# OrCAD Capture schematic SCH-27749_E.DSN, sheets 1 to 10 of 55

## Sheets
1 Cover Page: title: T4240RDB-PB; rev: E; note: SCH-27749     /     PDF: SPF-27749
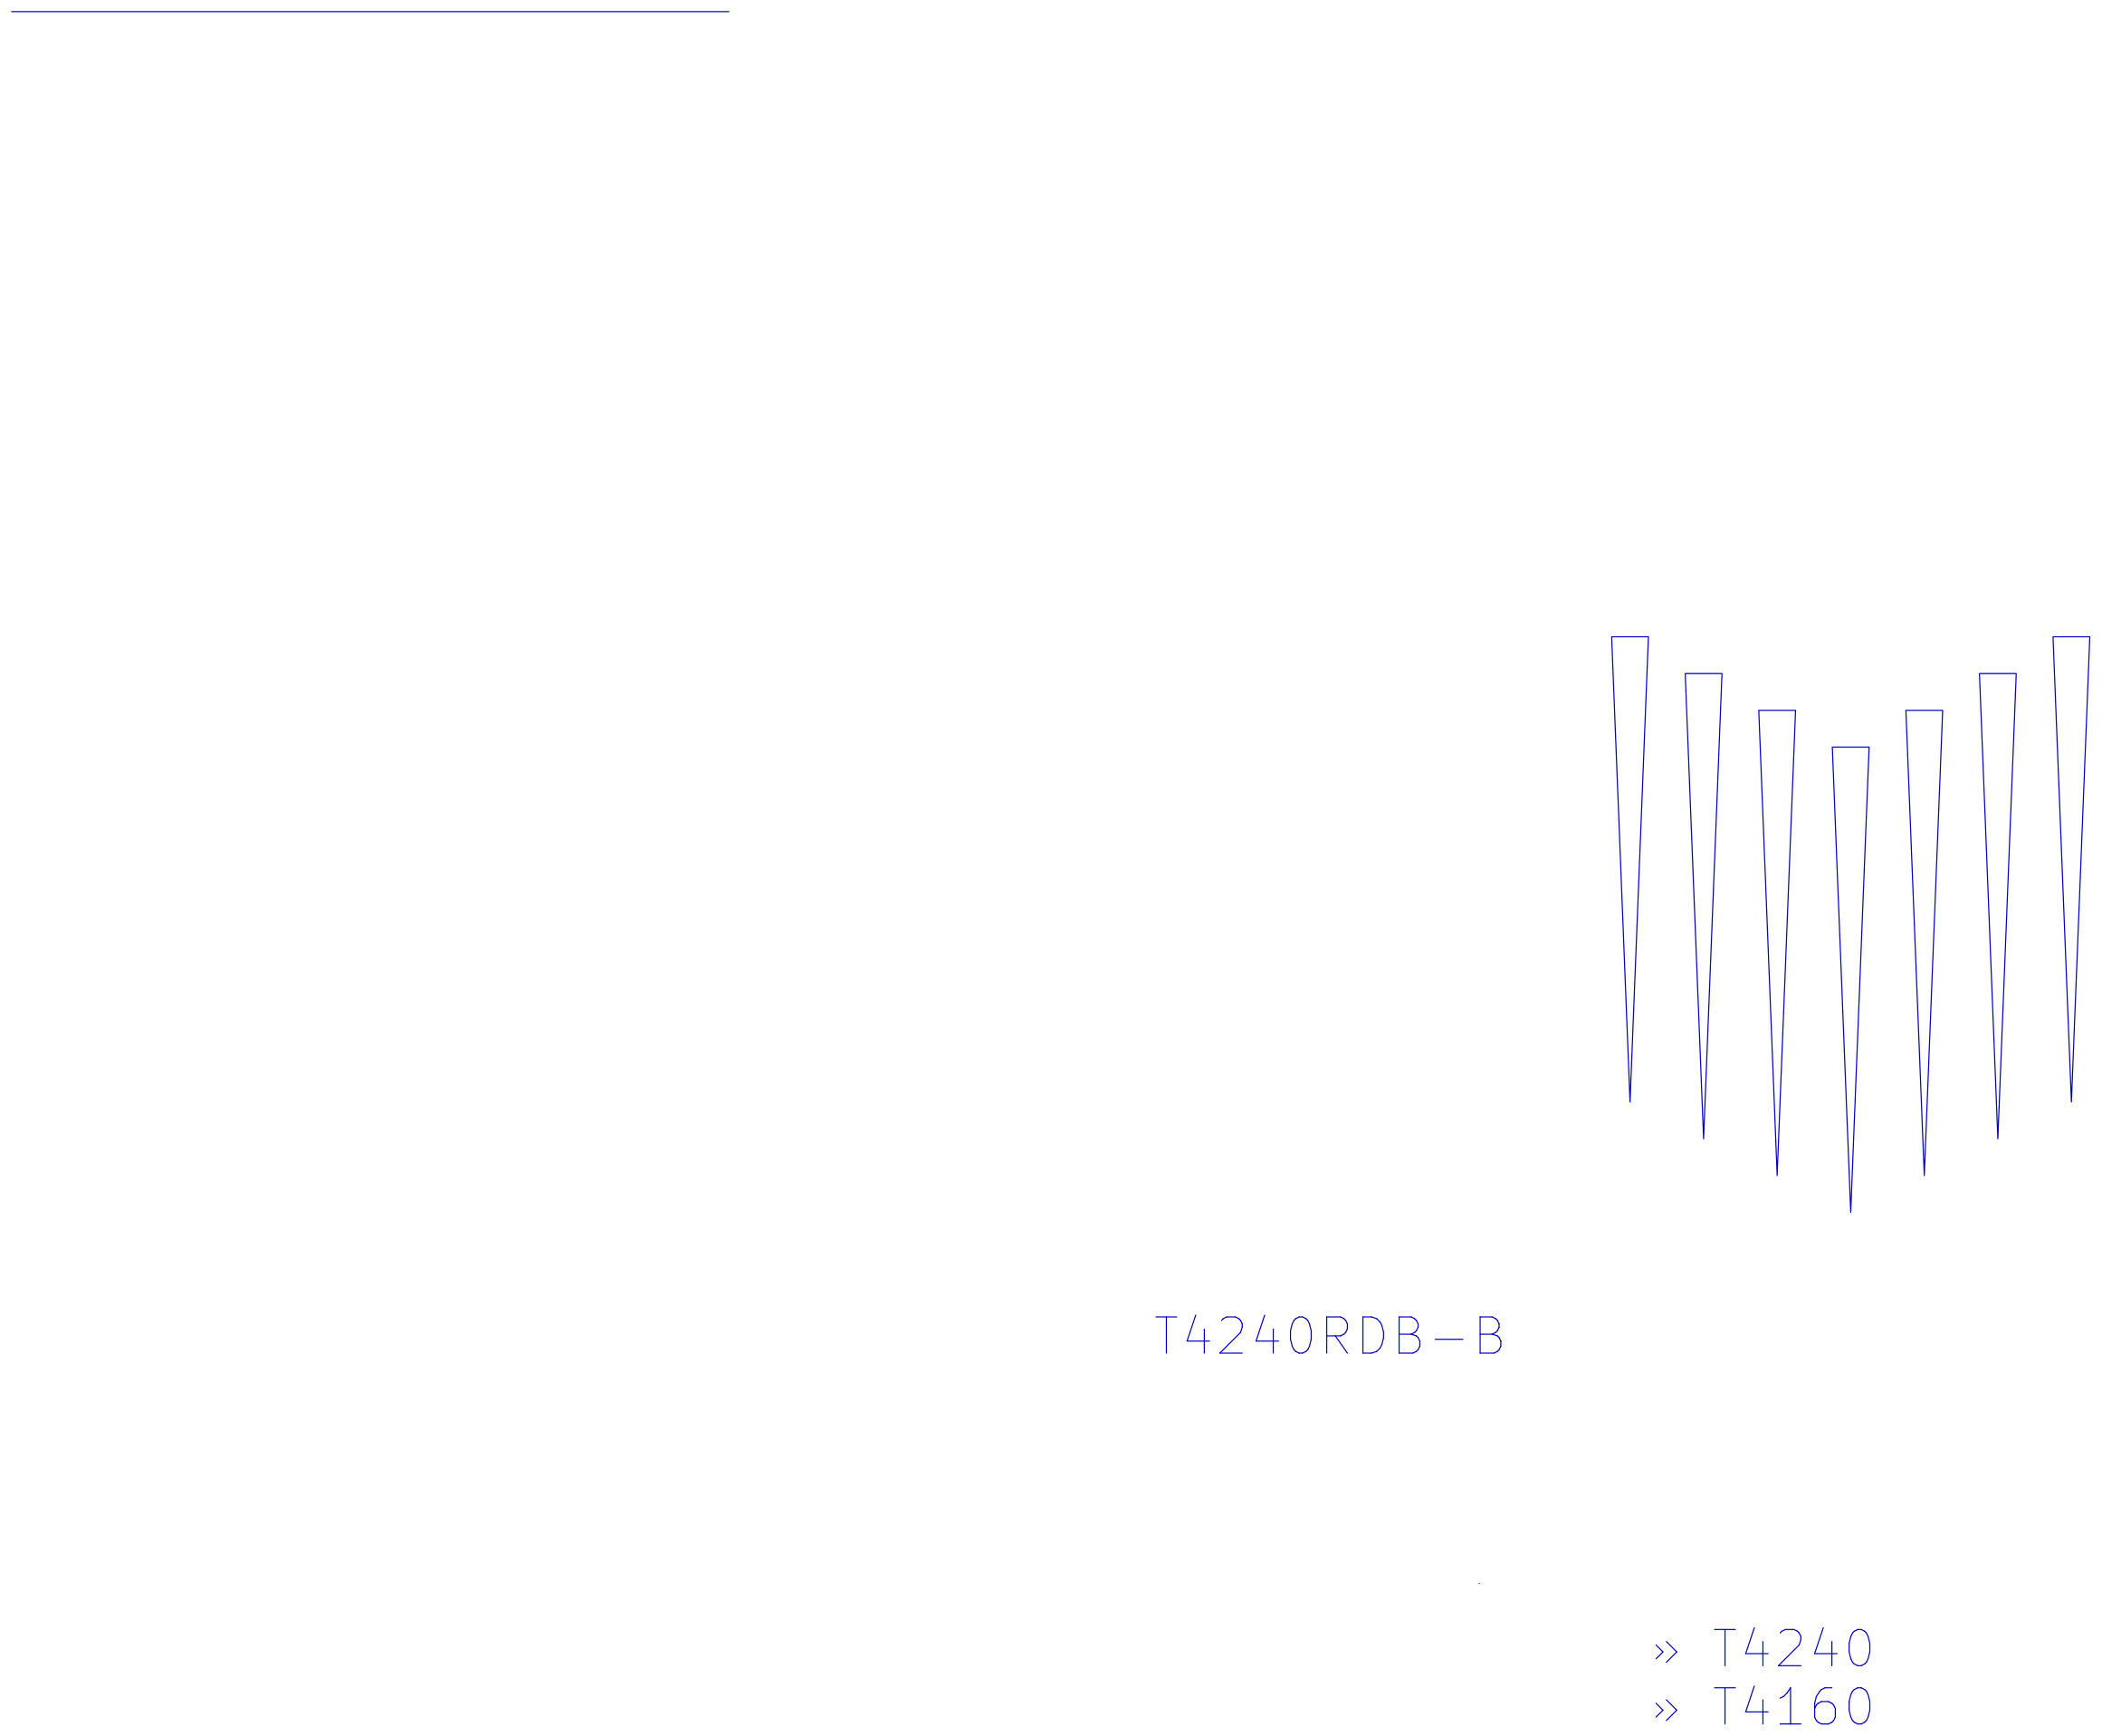
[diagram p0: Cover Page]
2 Revision Control
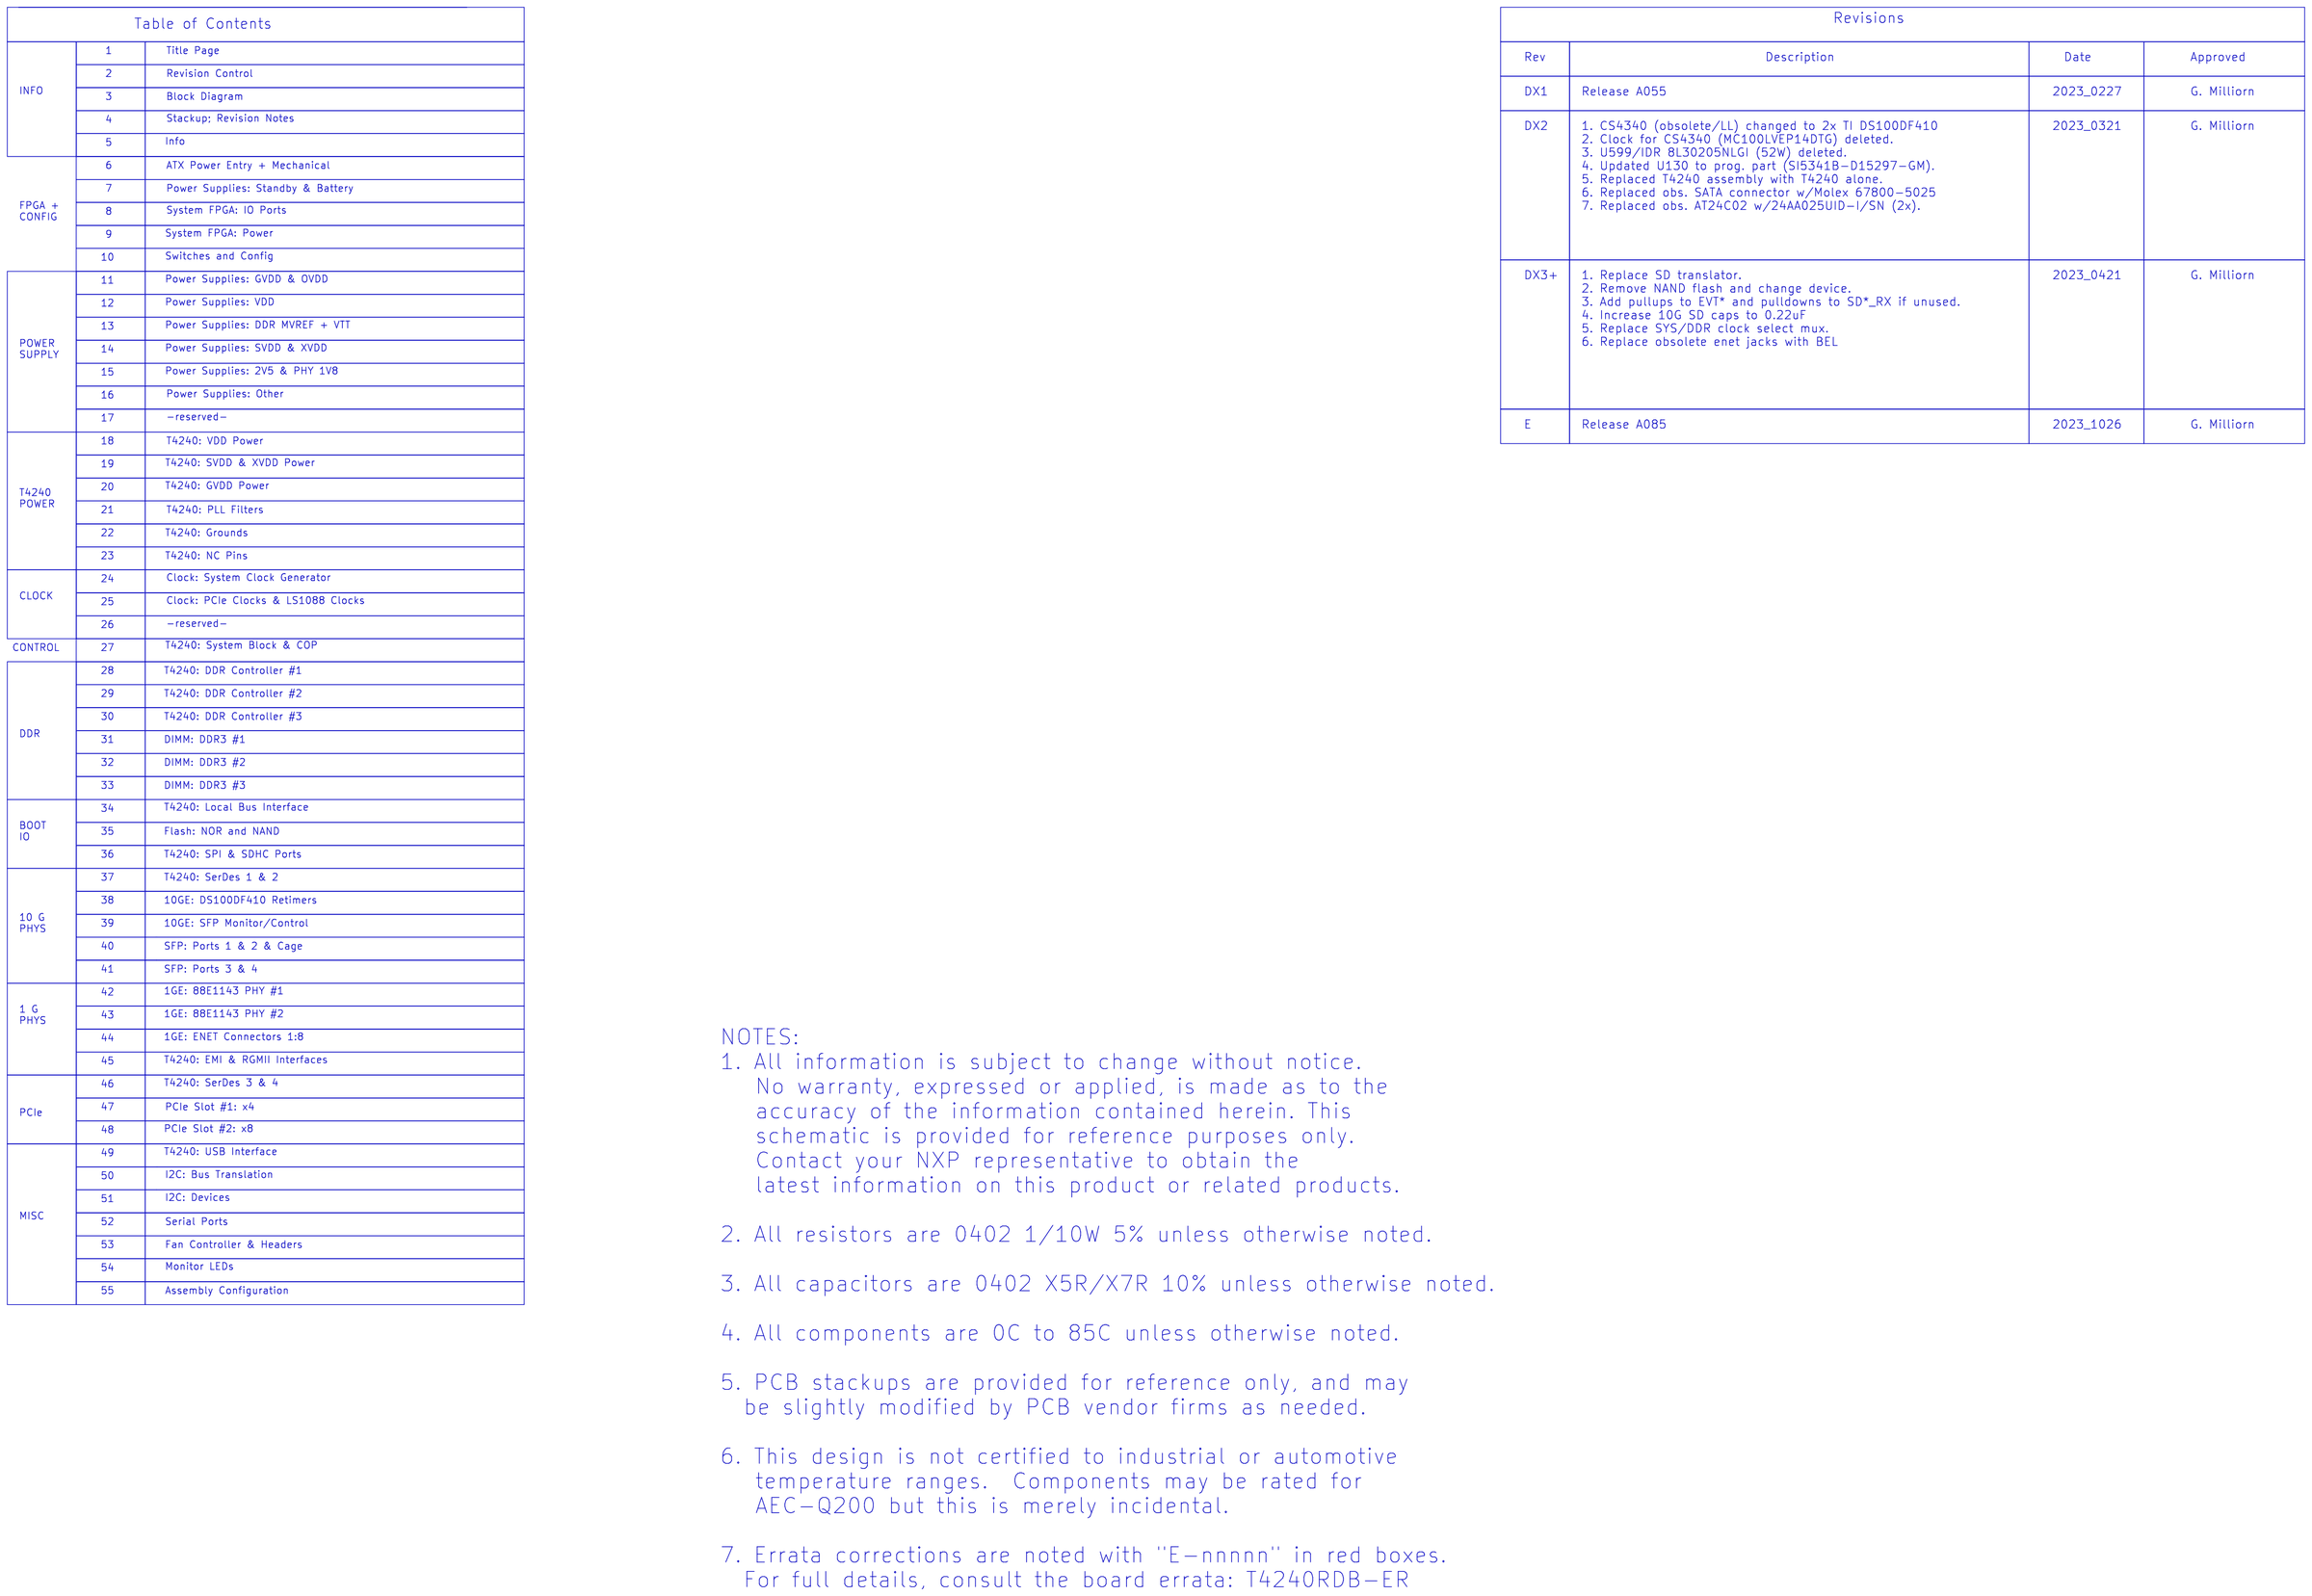
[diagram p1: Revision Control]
3 Block Diagram
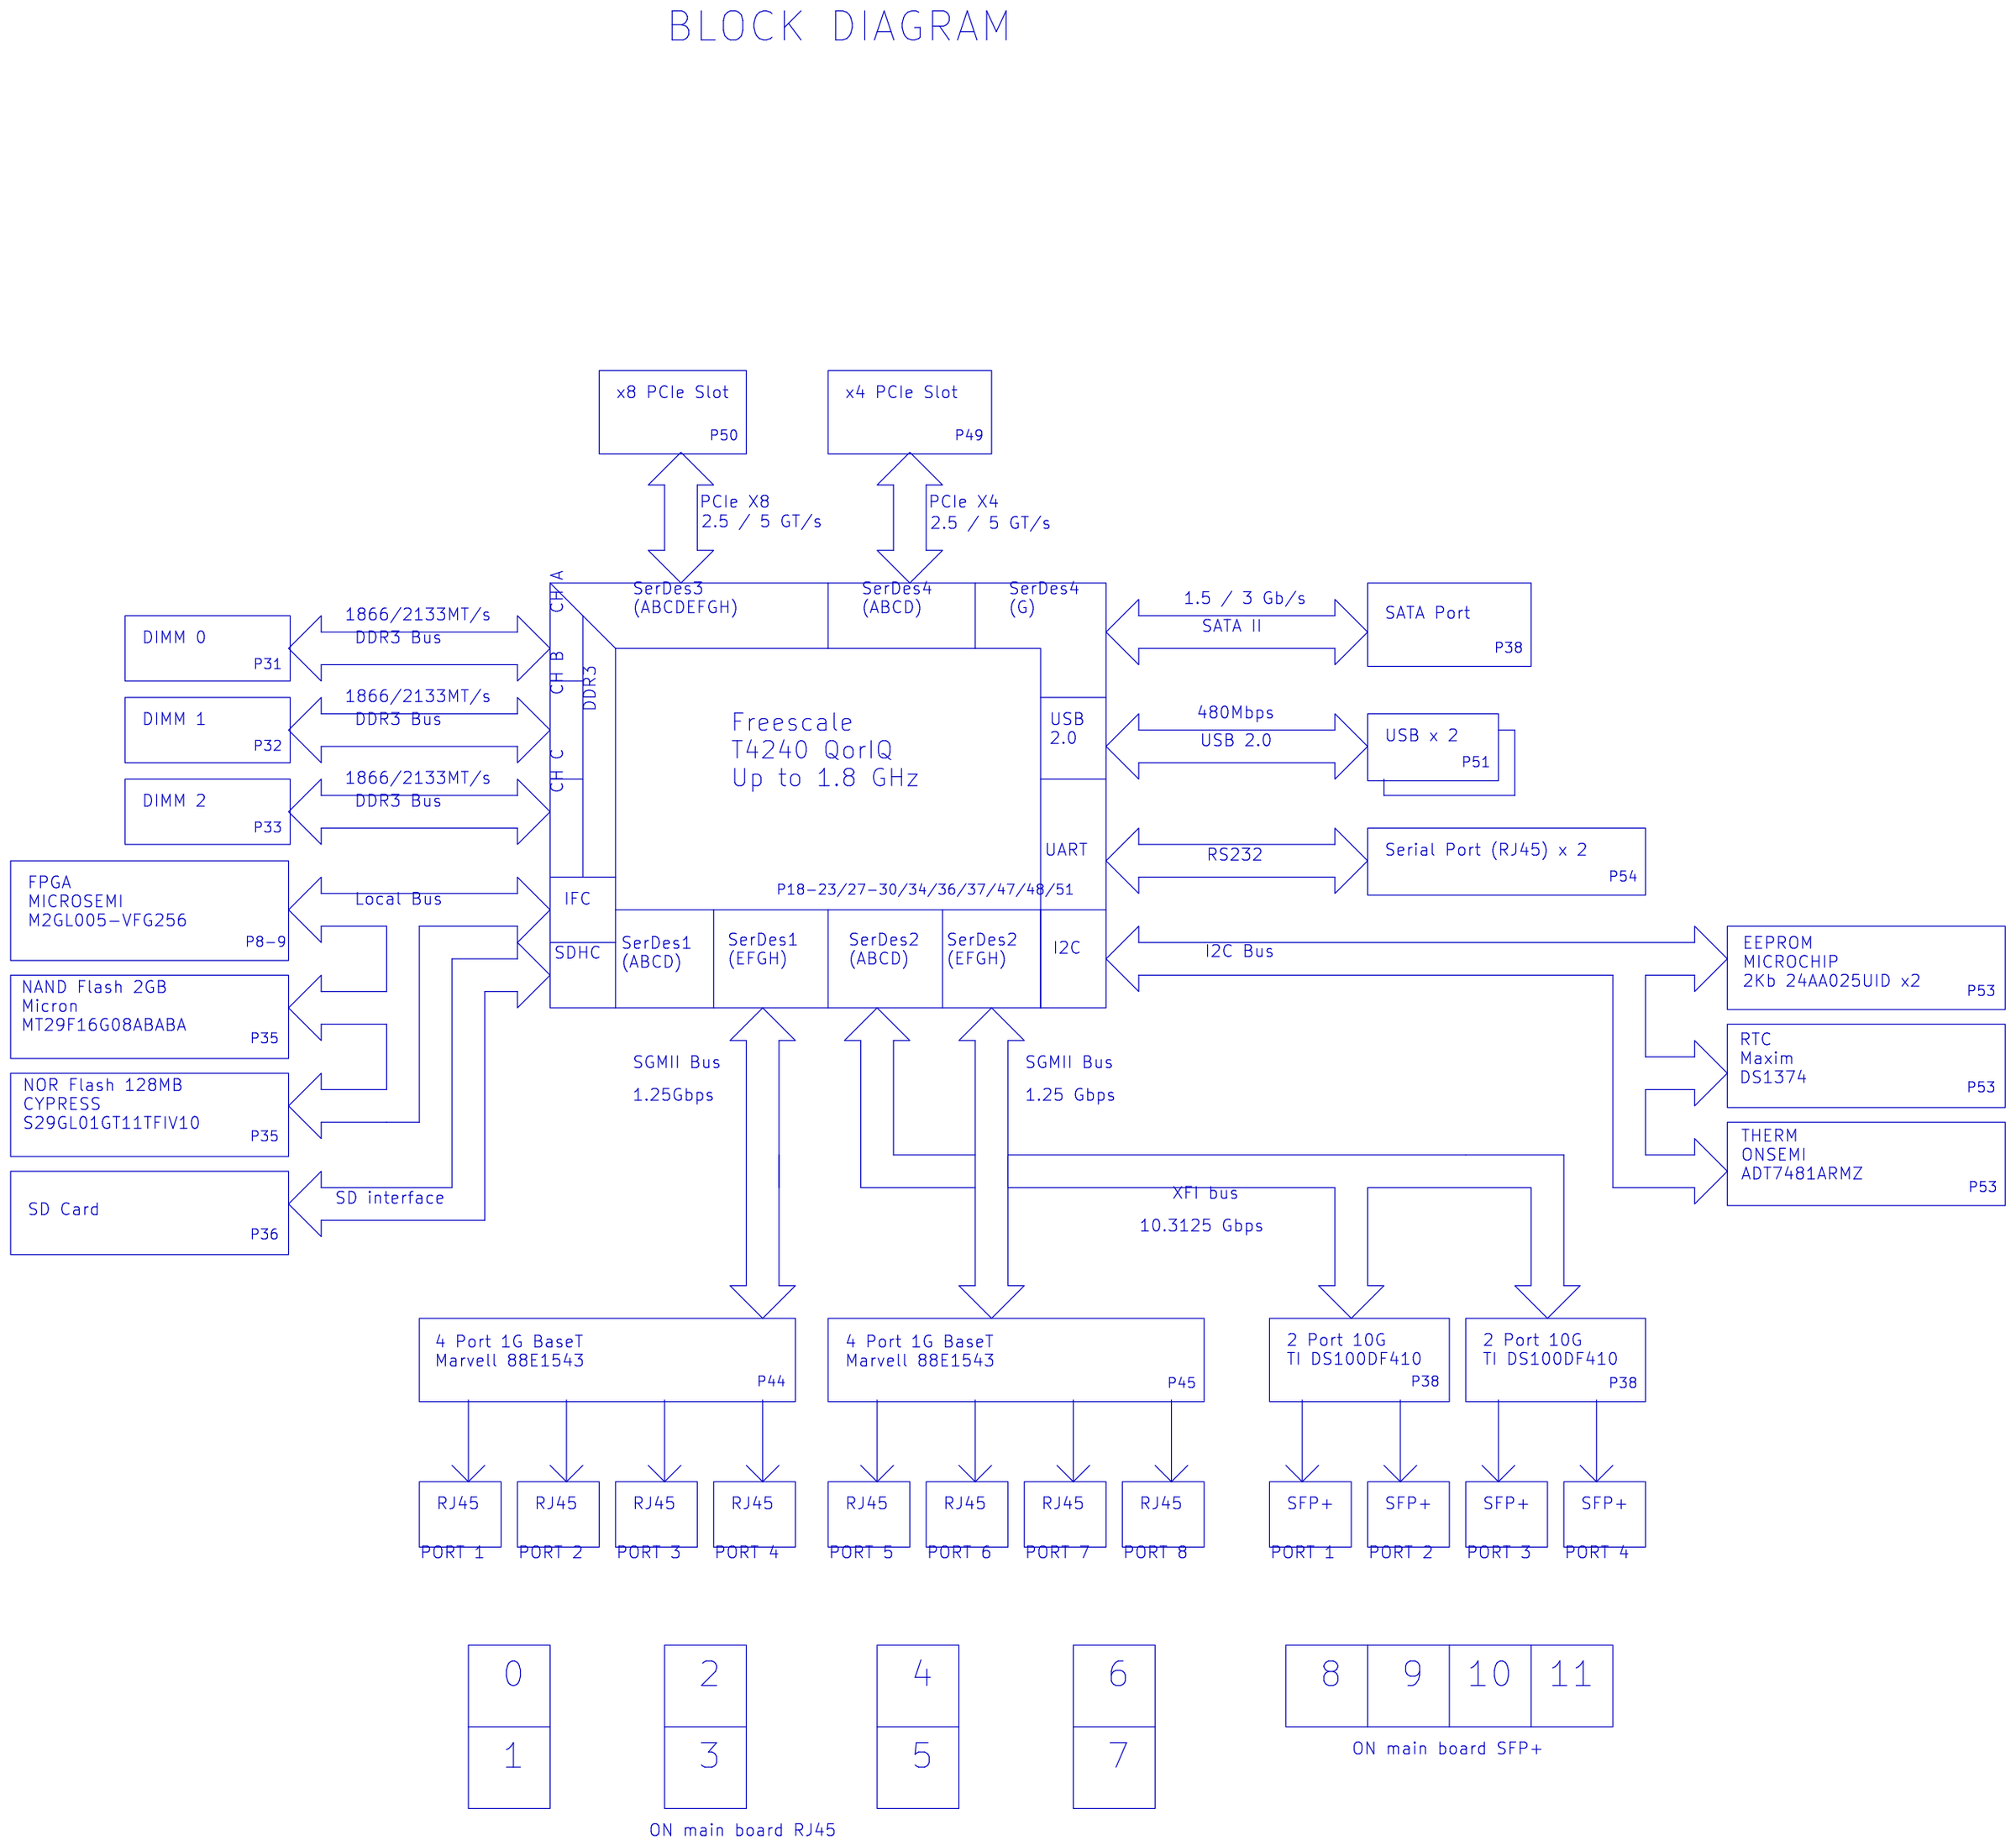
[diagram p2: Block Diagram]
4 Stackup
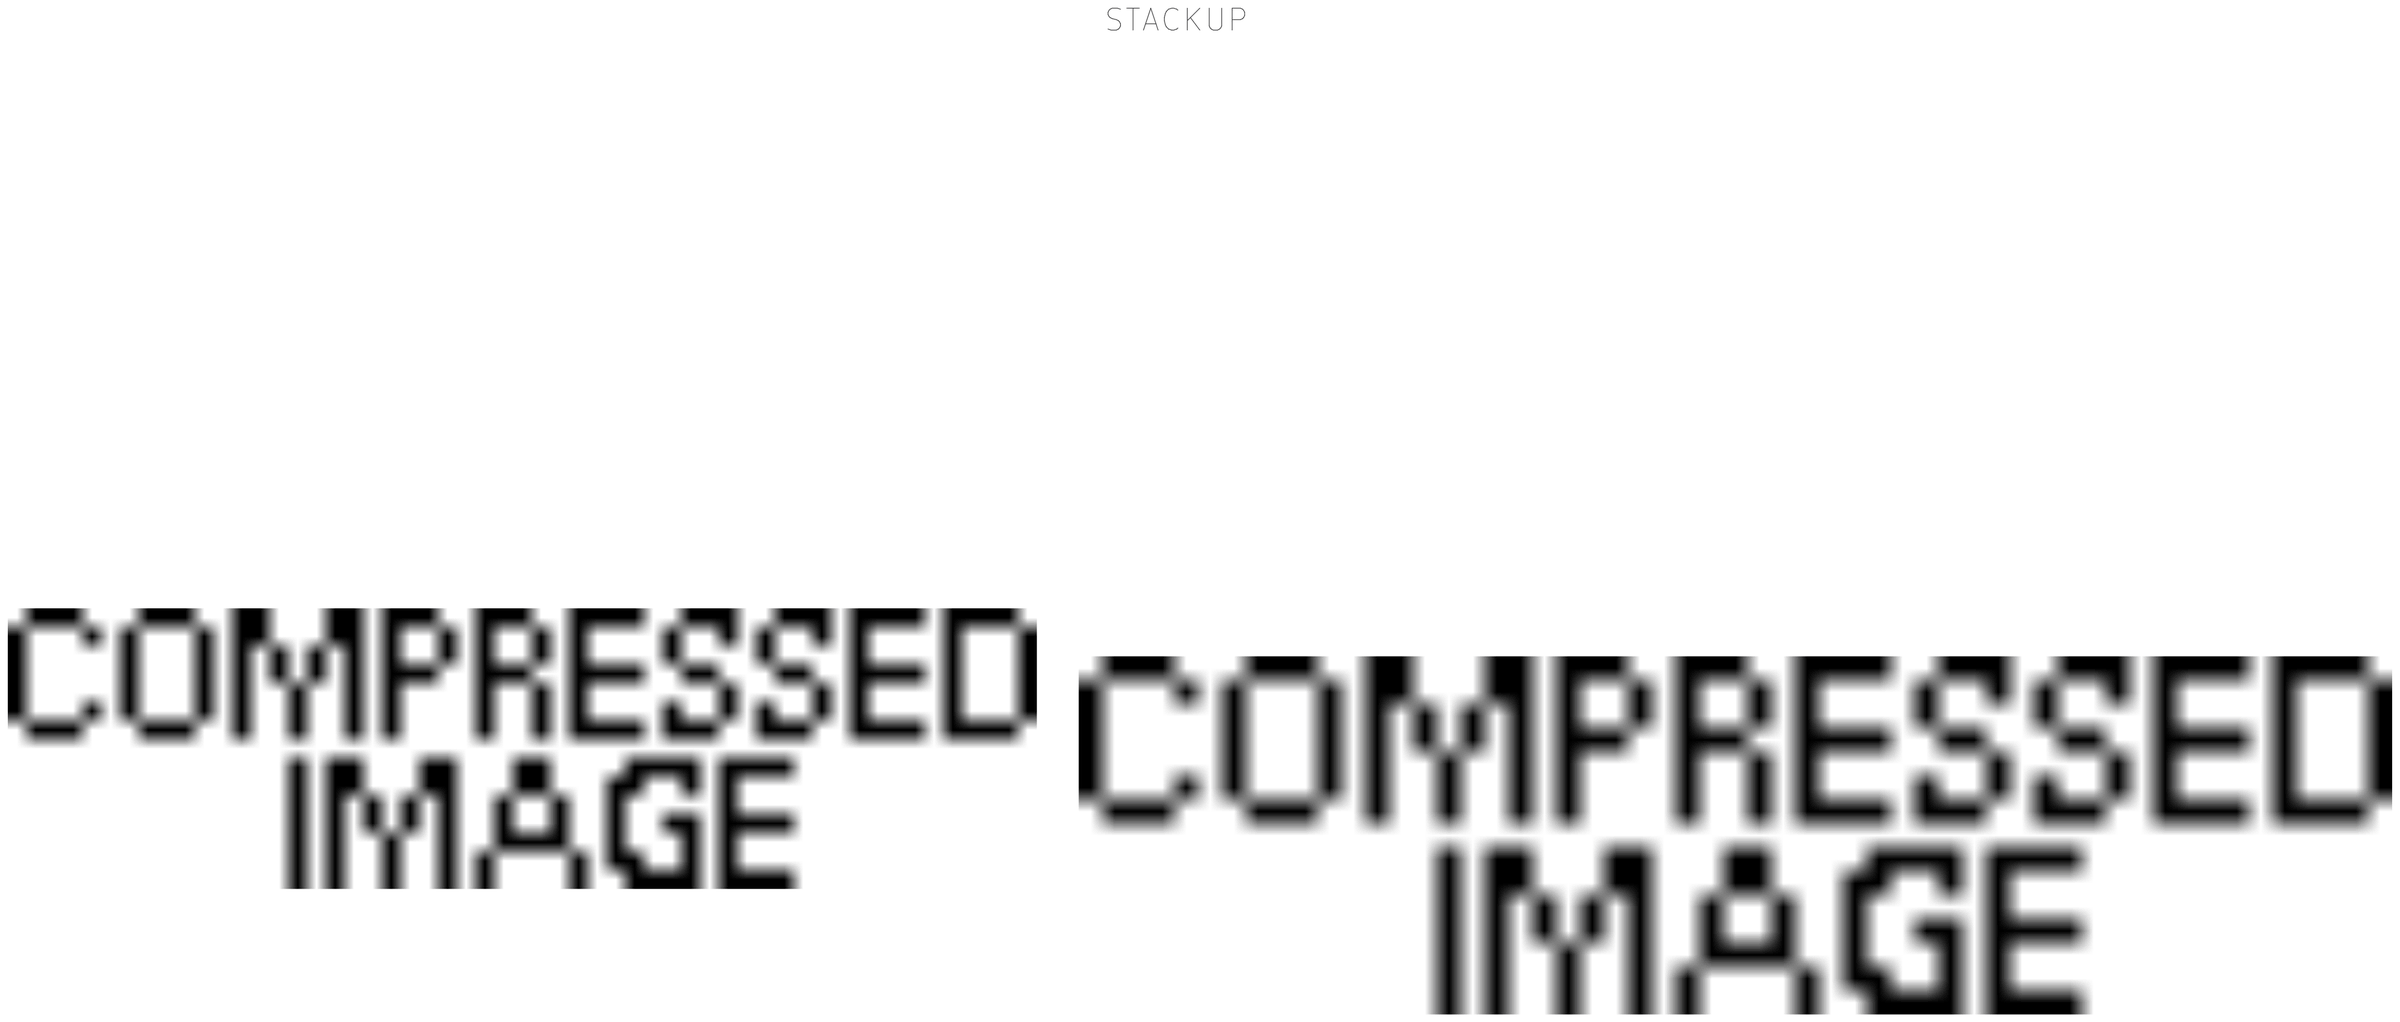
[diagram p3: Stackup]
5 Info
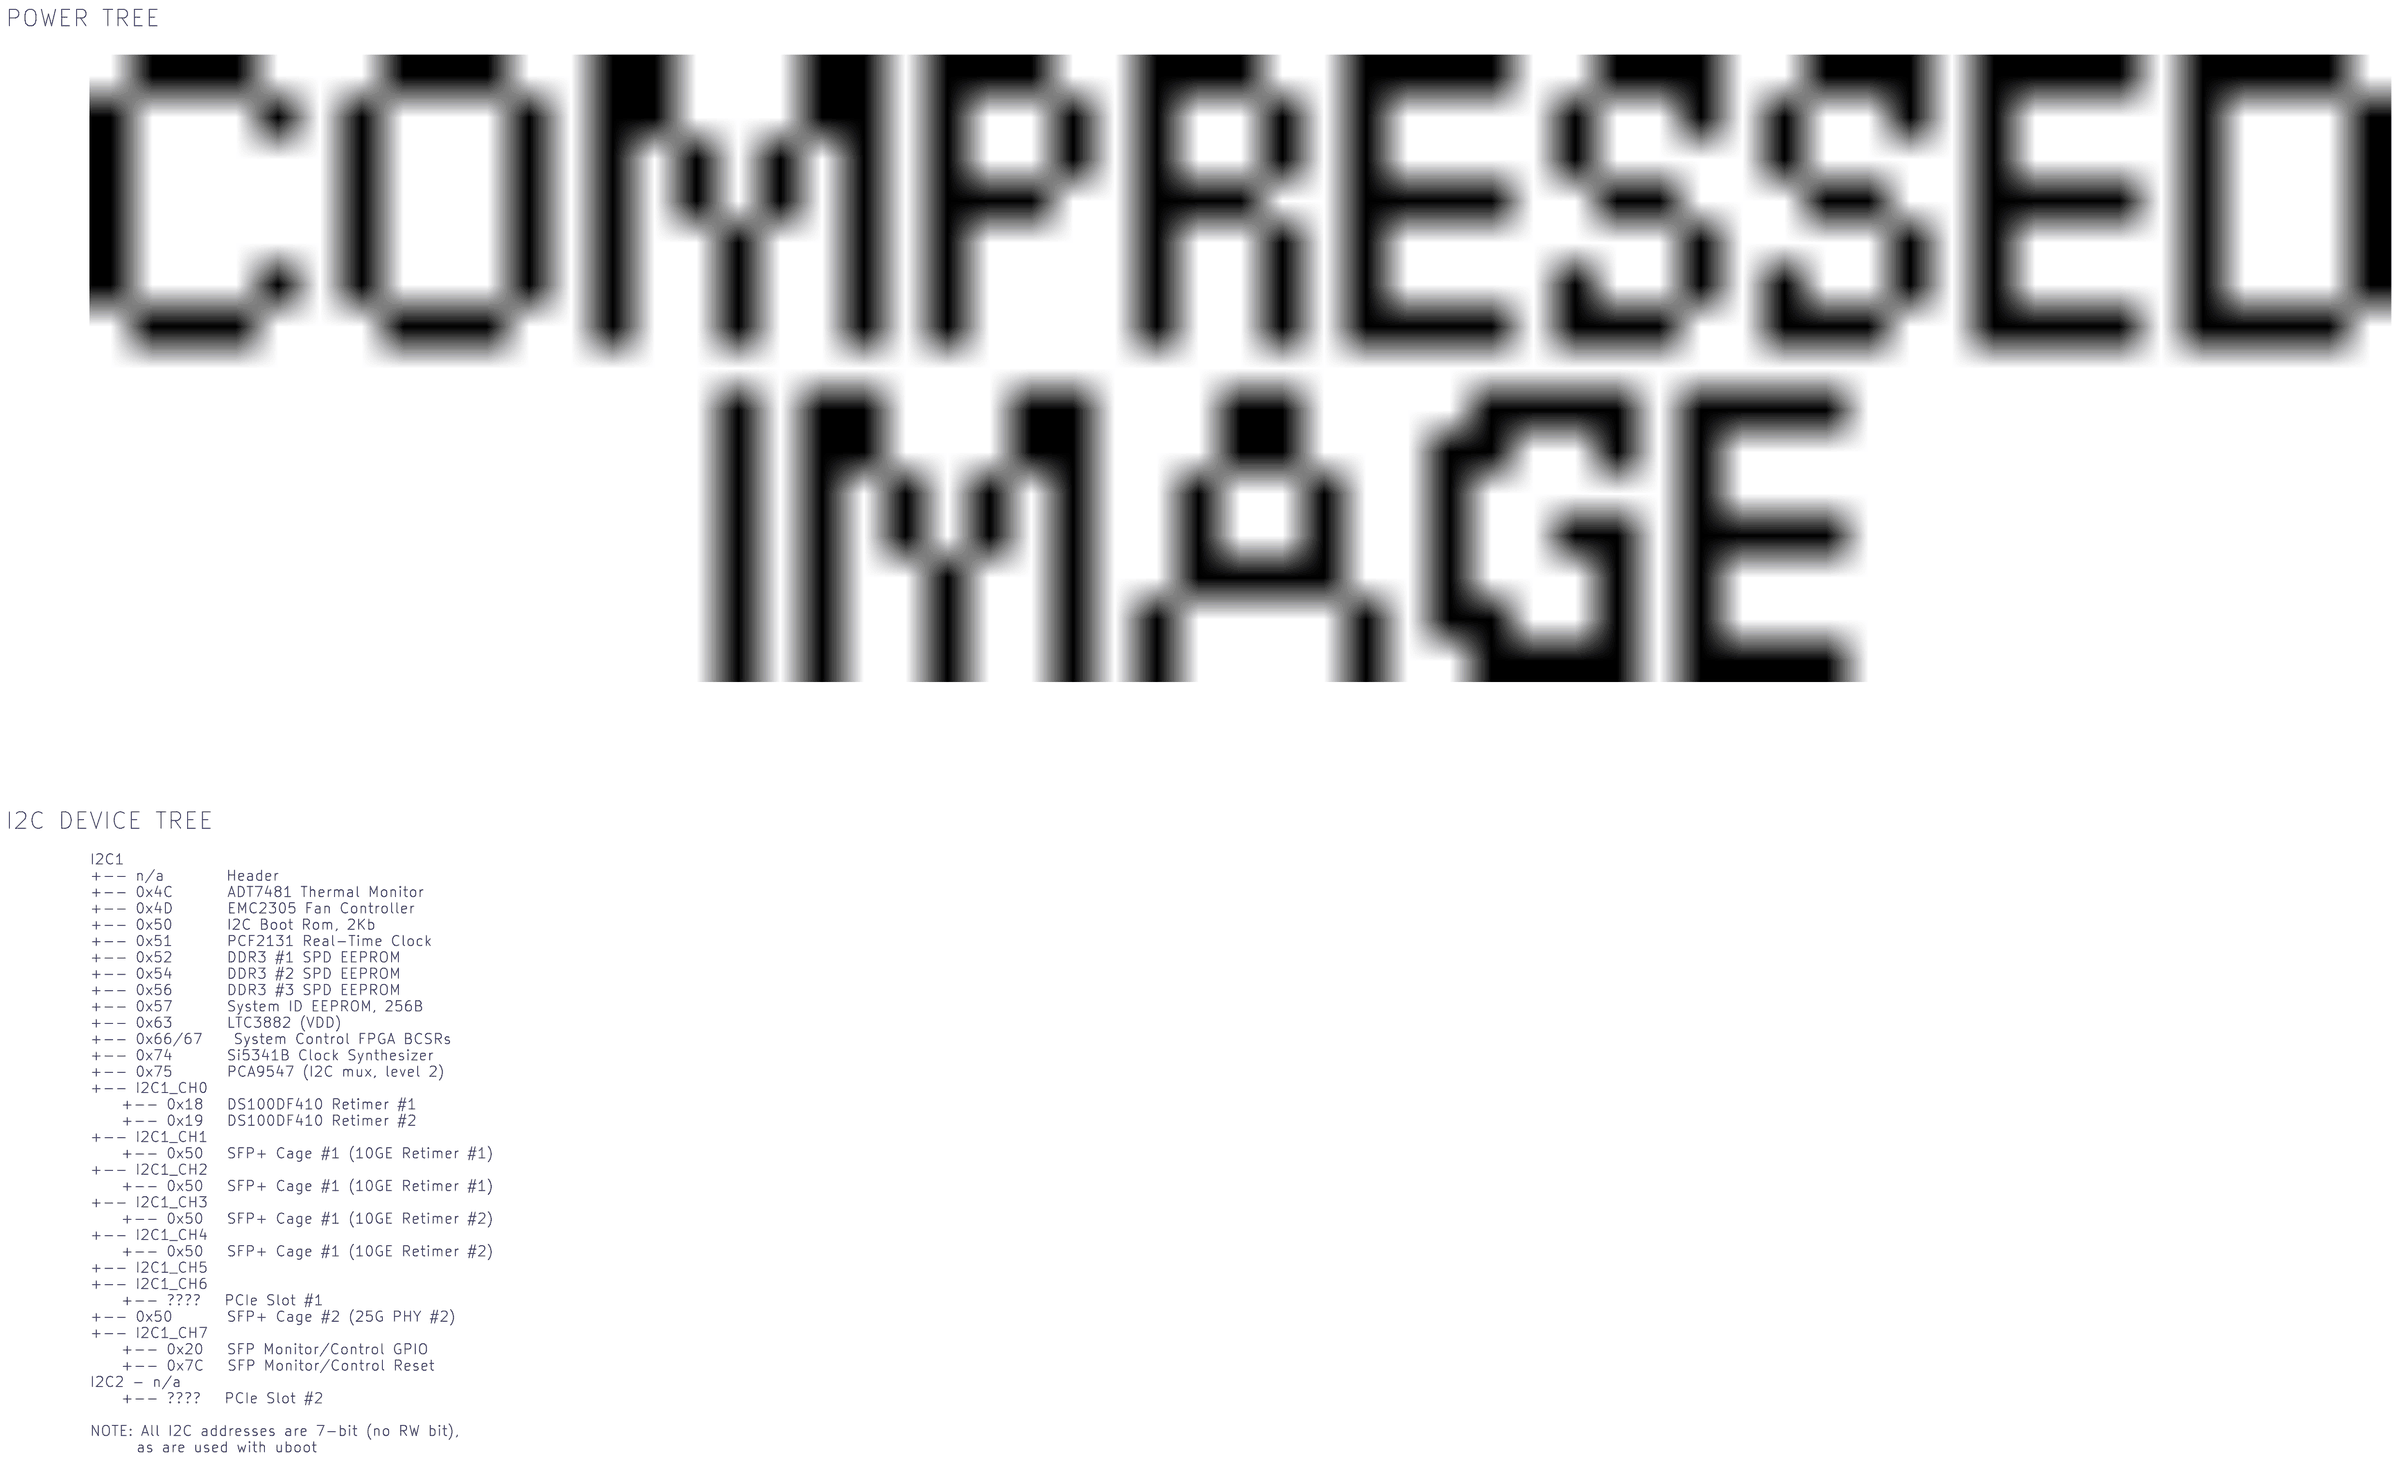
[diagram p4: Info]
6 Power Entry & Mechanical: size C
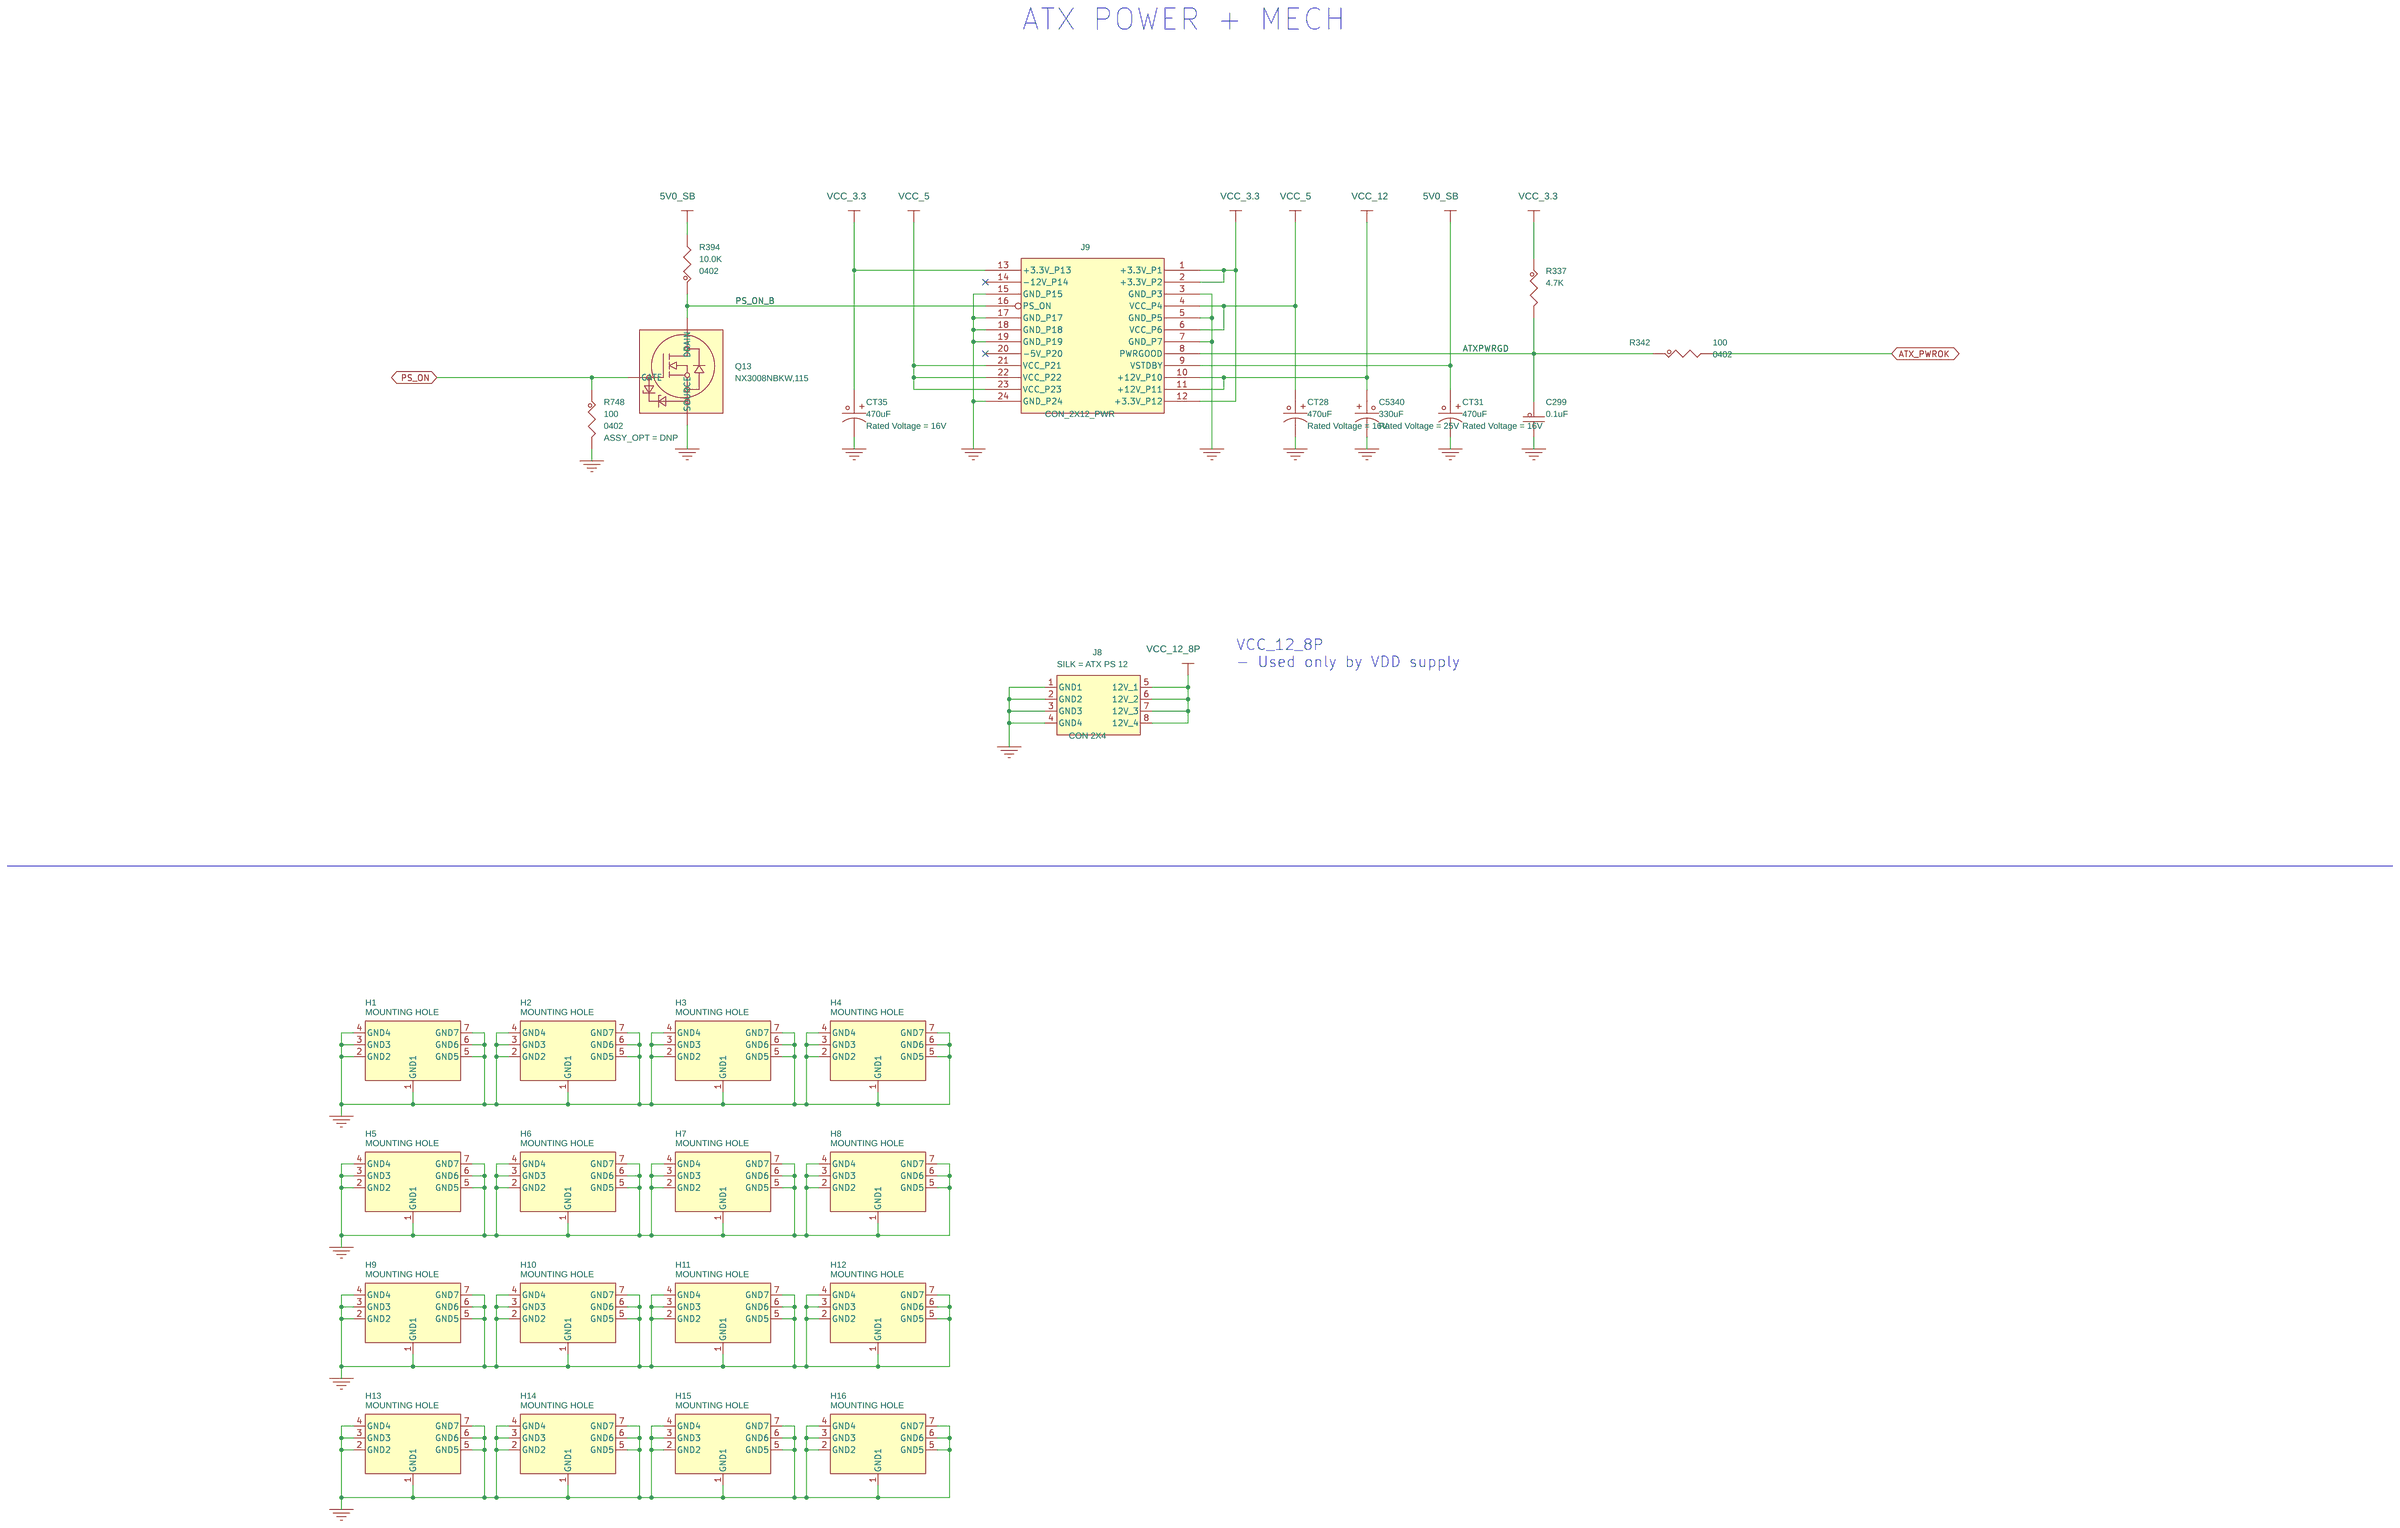
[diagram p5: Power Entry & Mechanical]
7 Standby Power: size C
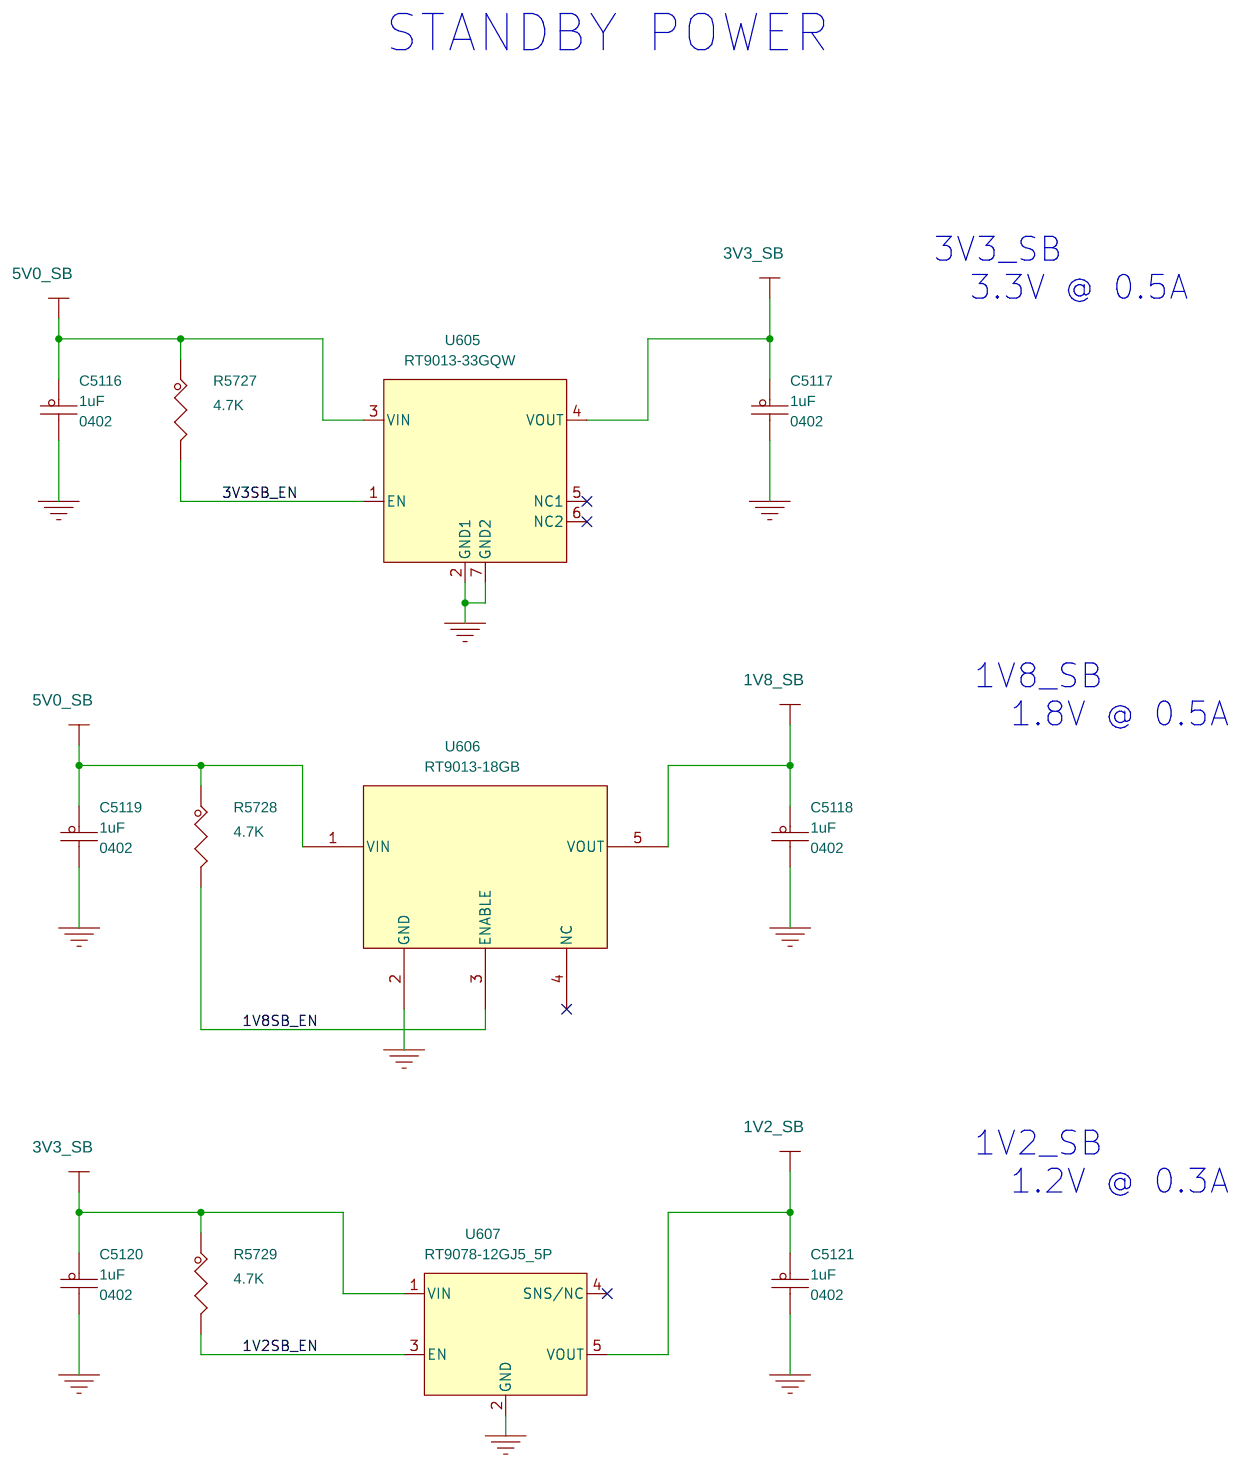
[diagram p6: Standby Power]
8 System FPGA IO Ports: size C
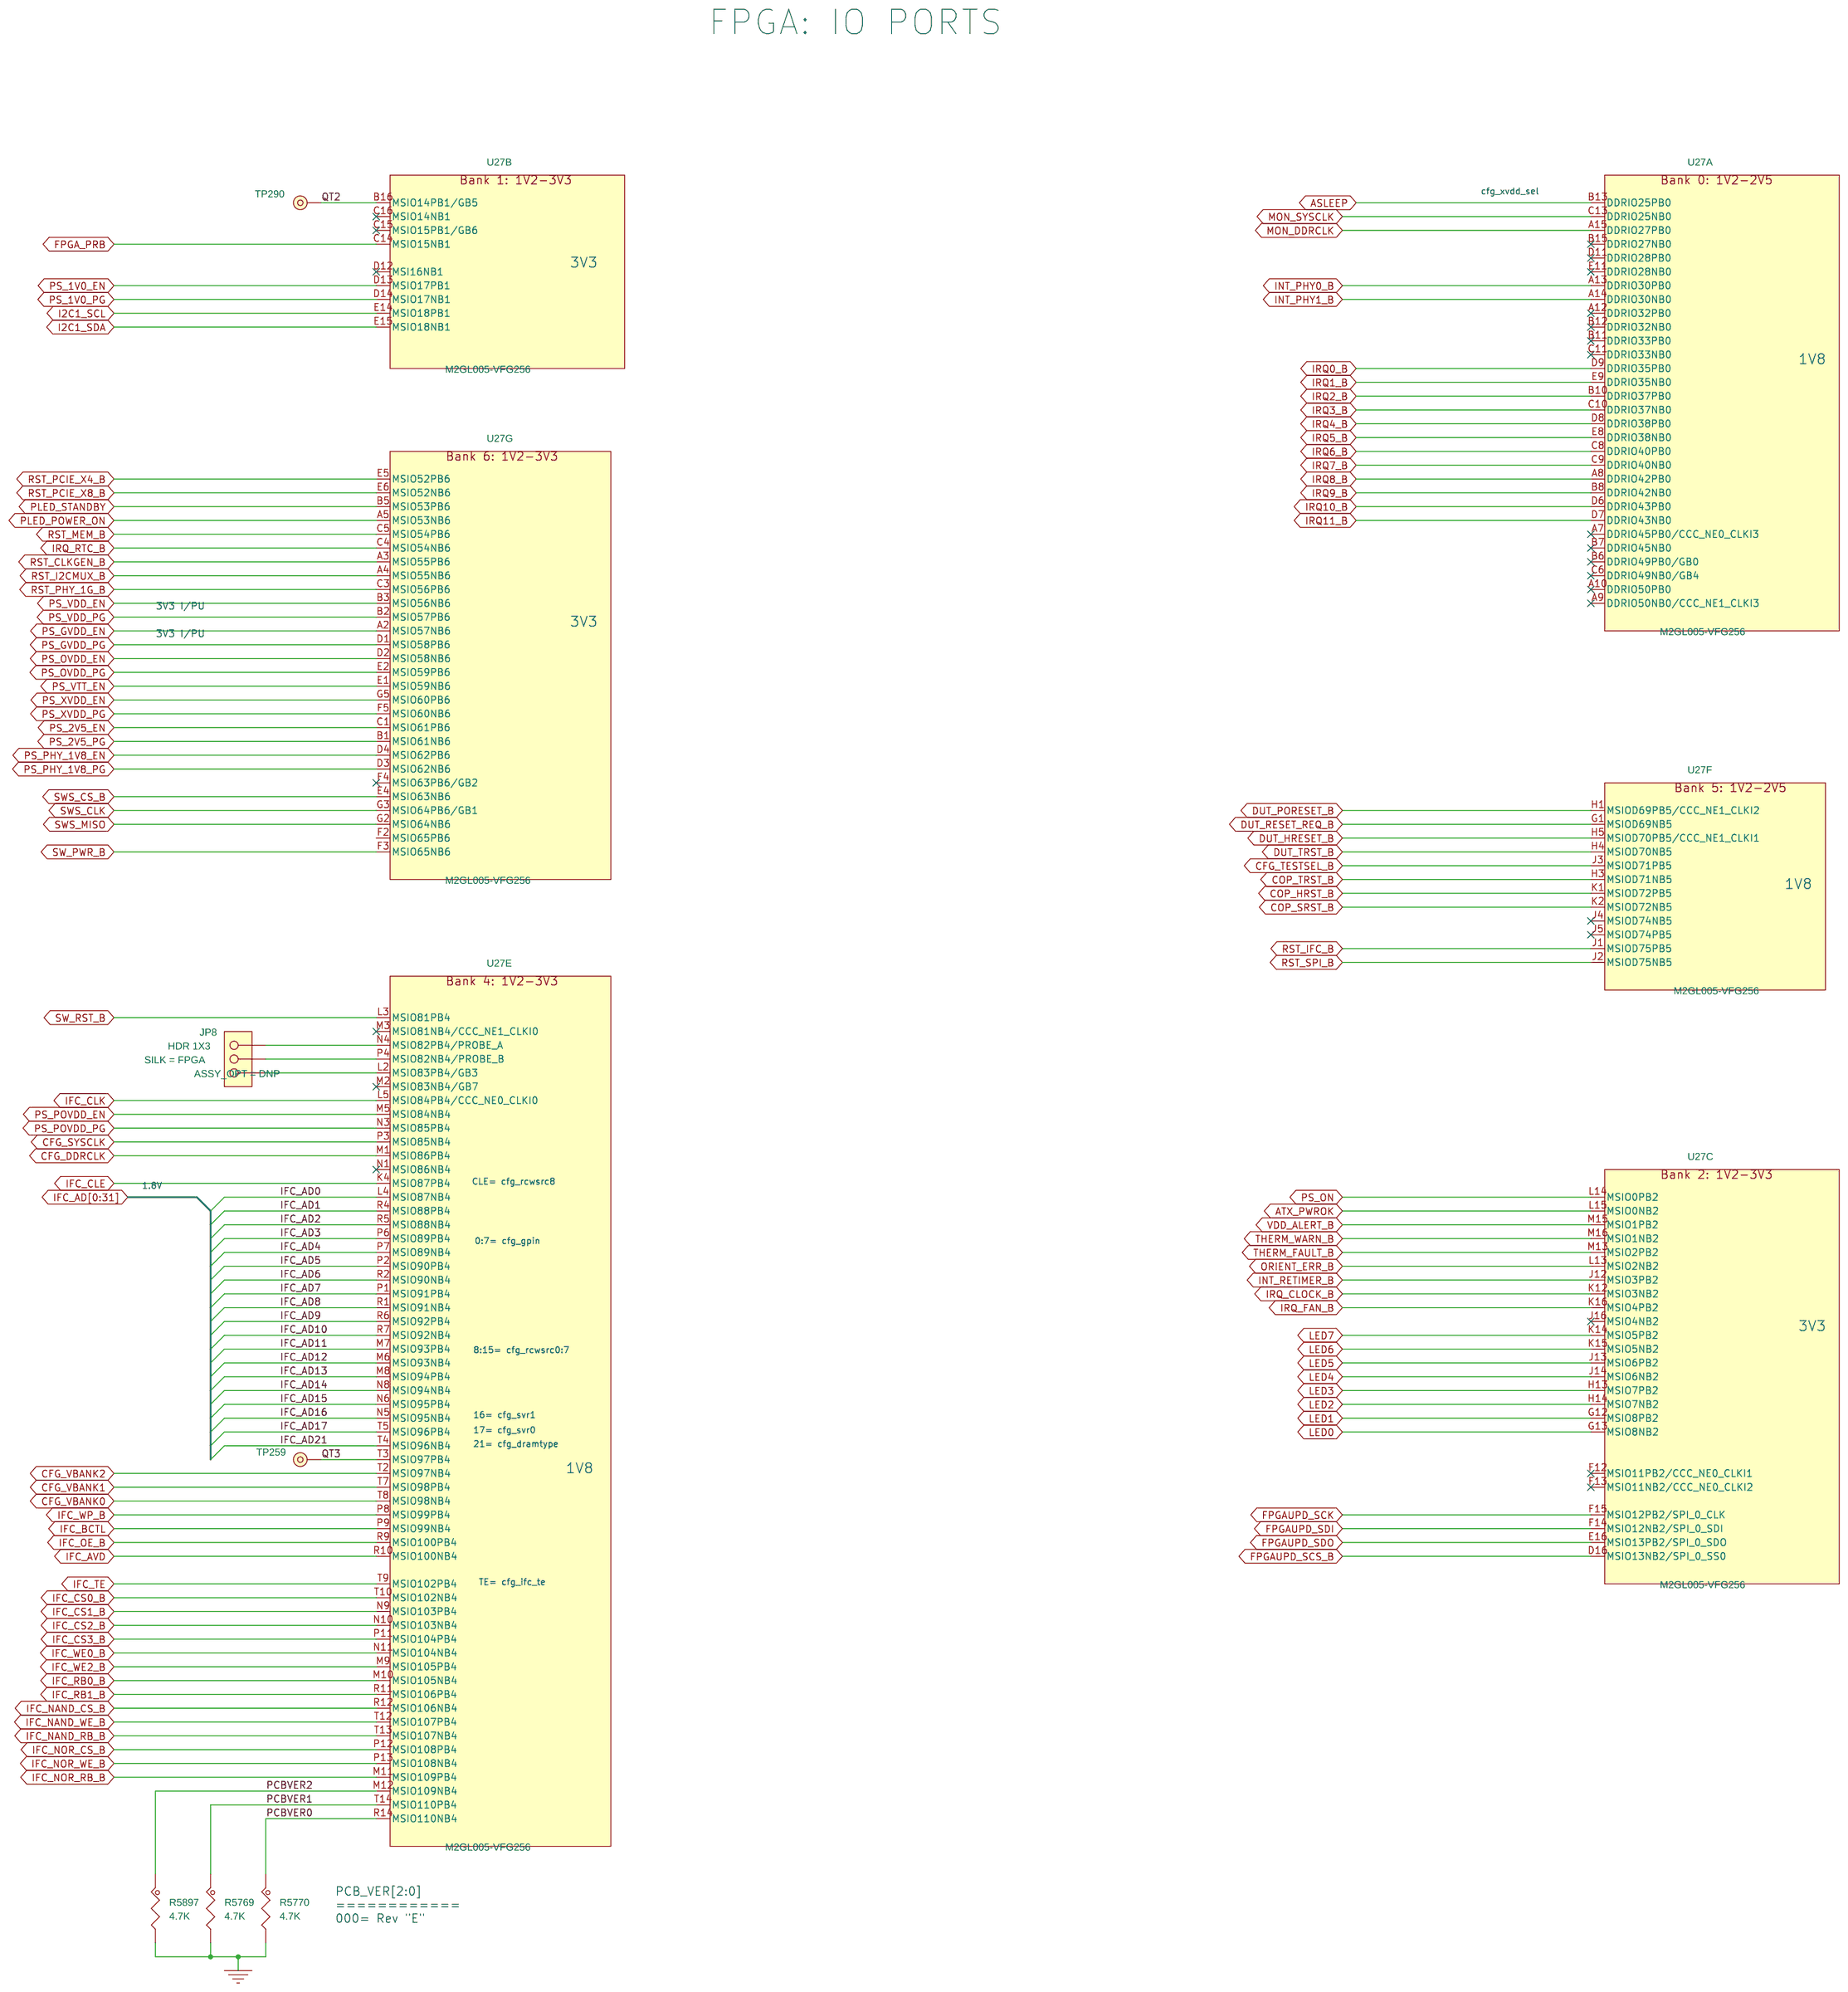
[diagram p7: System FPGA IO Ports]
9 System FPGA Power+Prog: size C
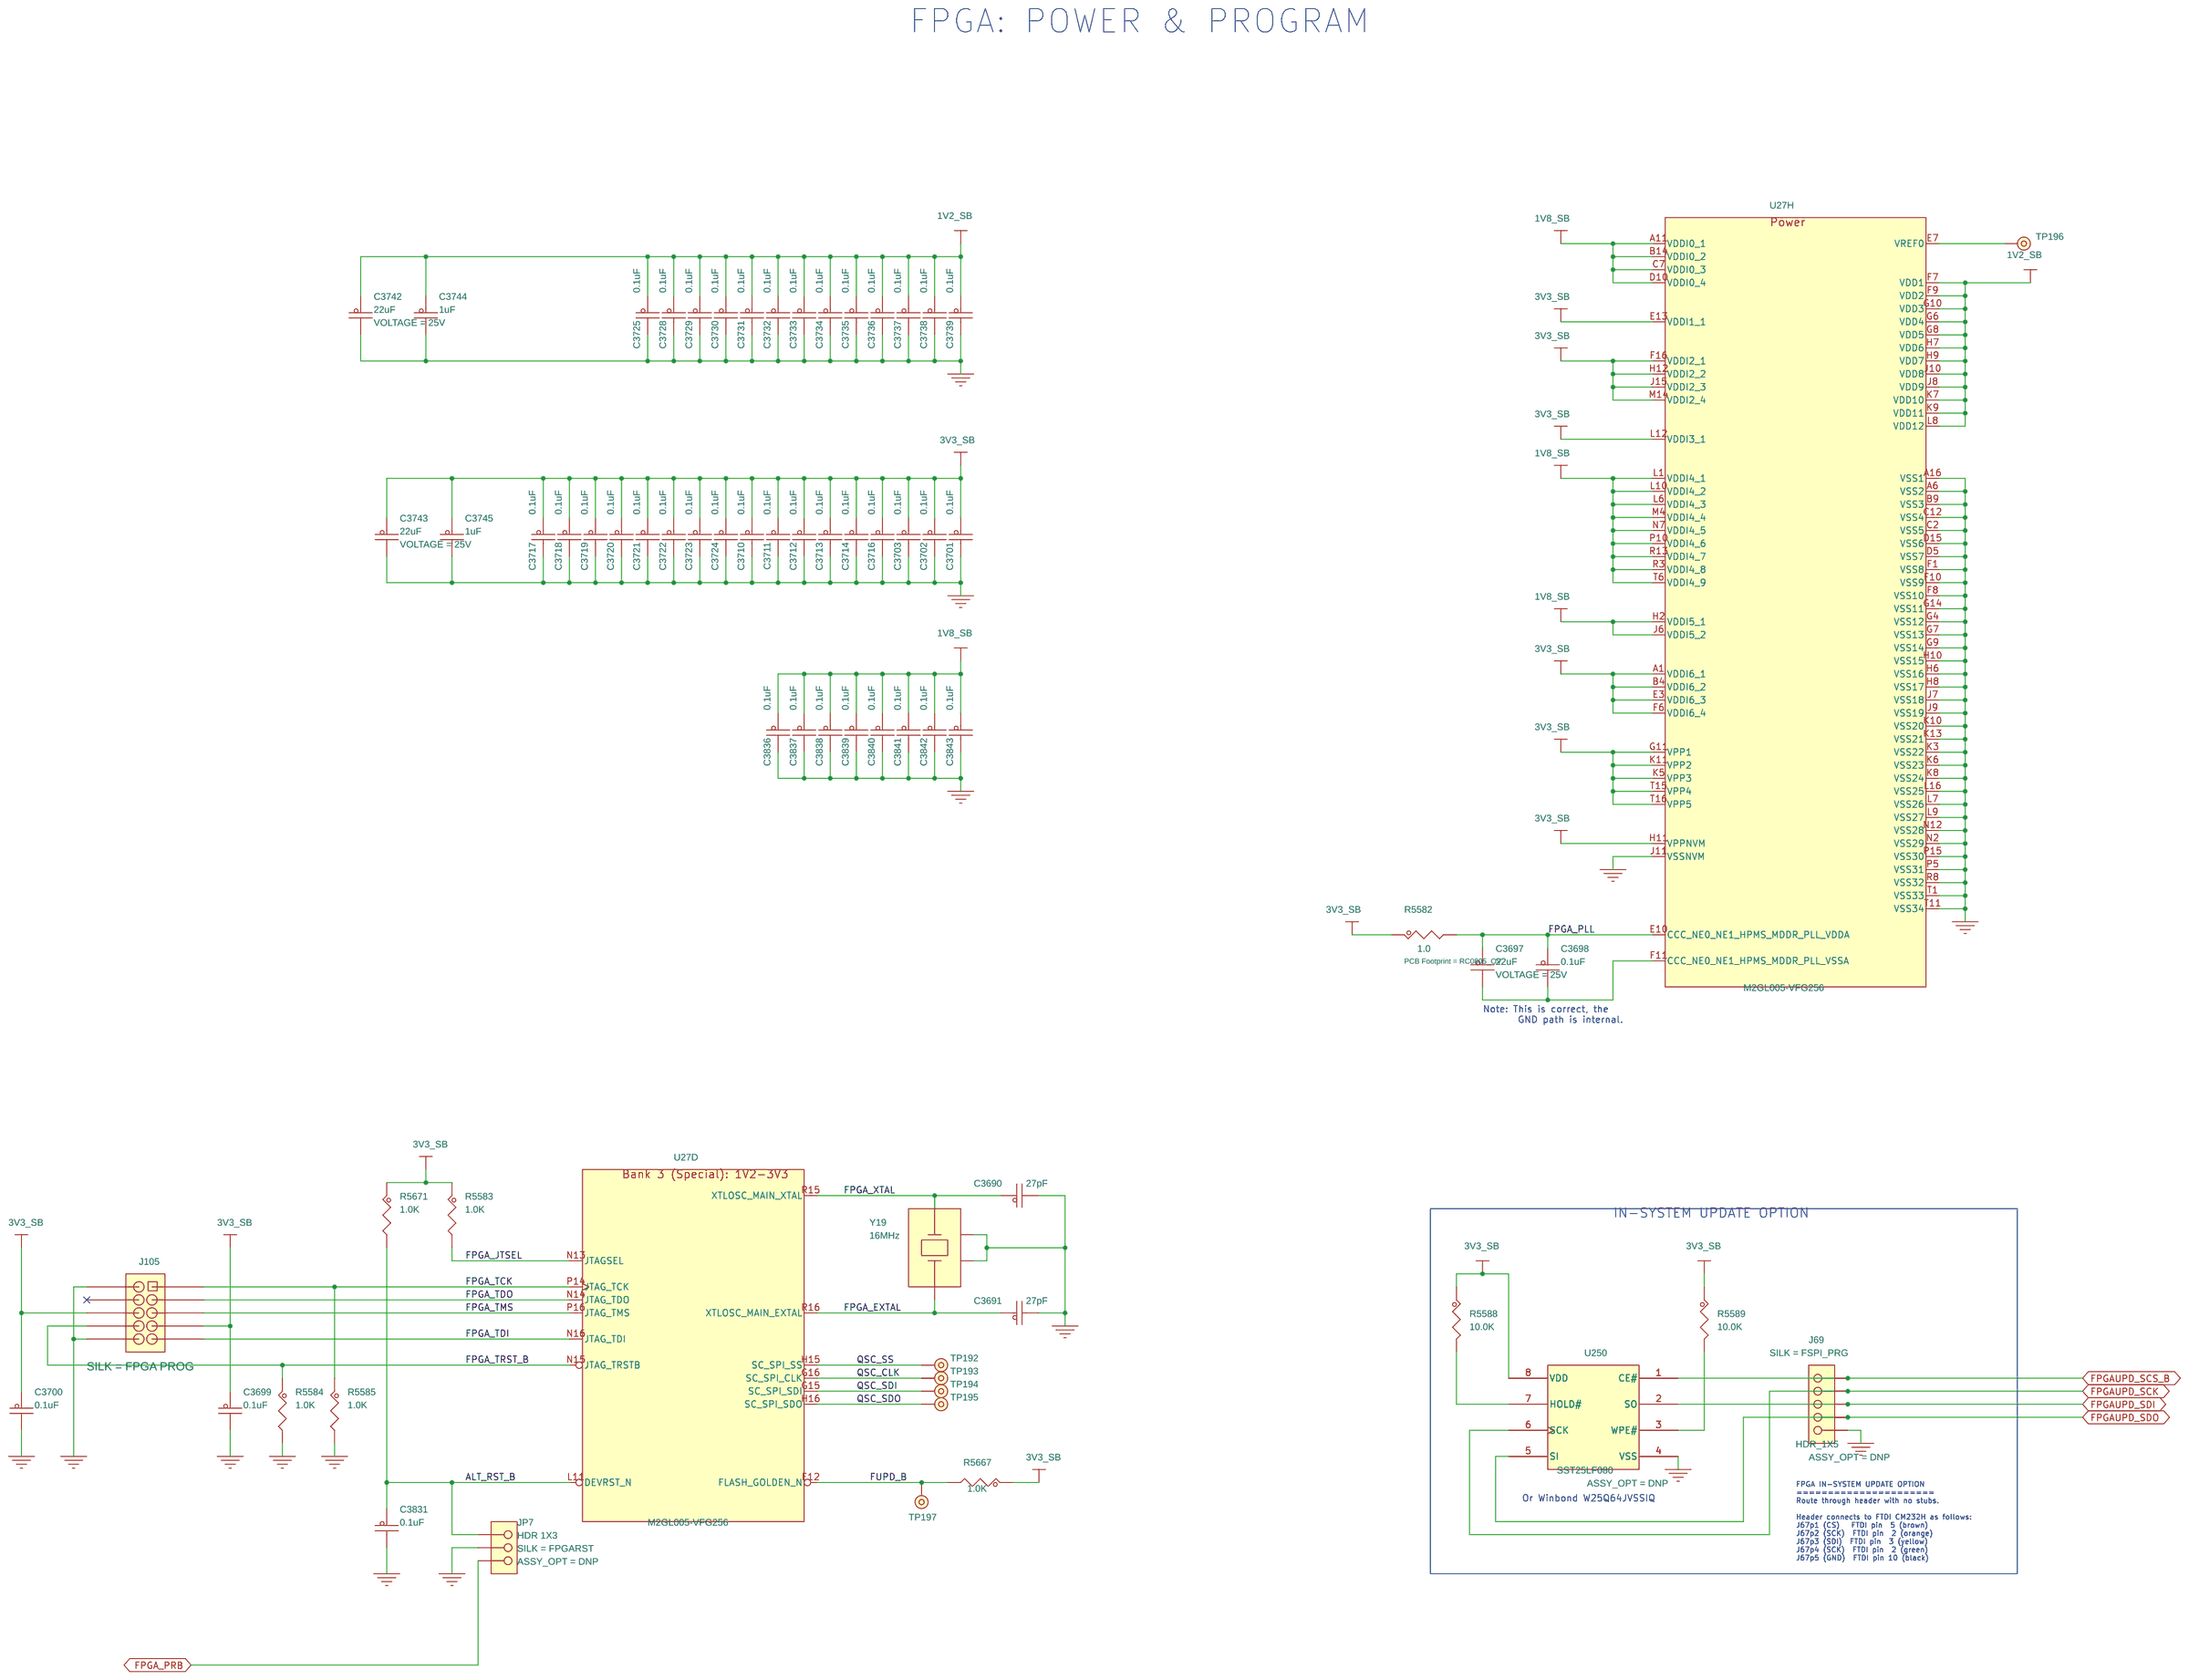
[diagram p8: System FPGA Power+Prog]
10 Switches and Config: size C
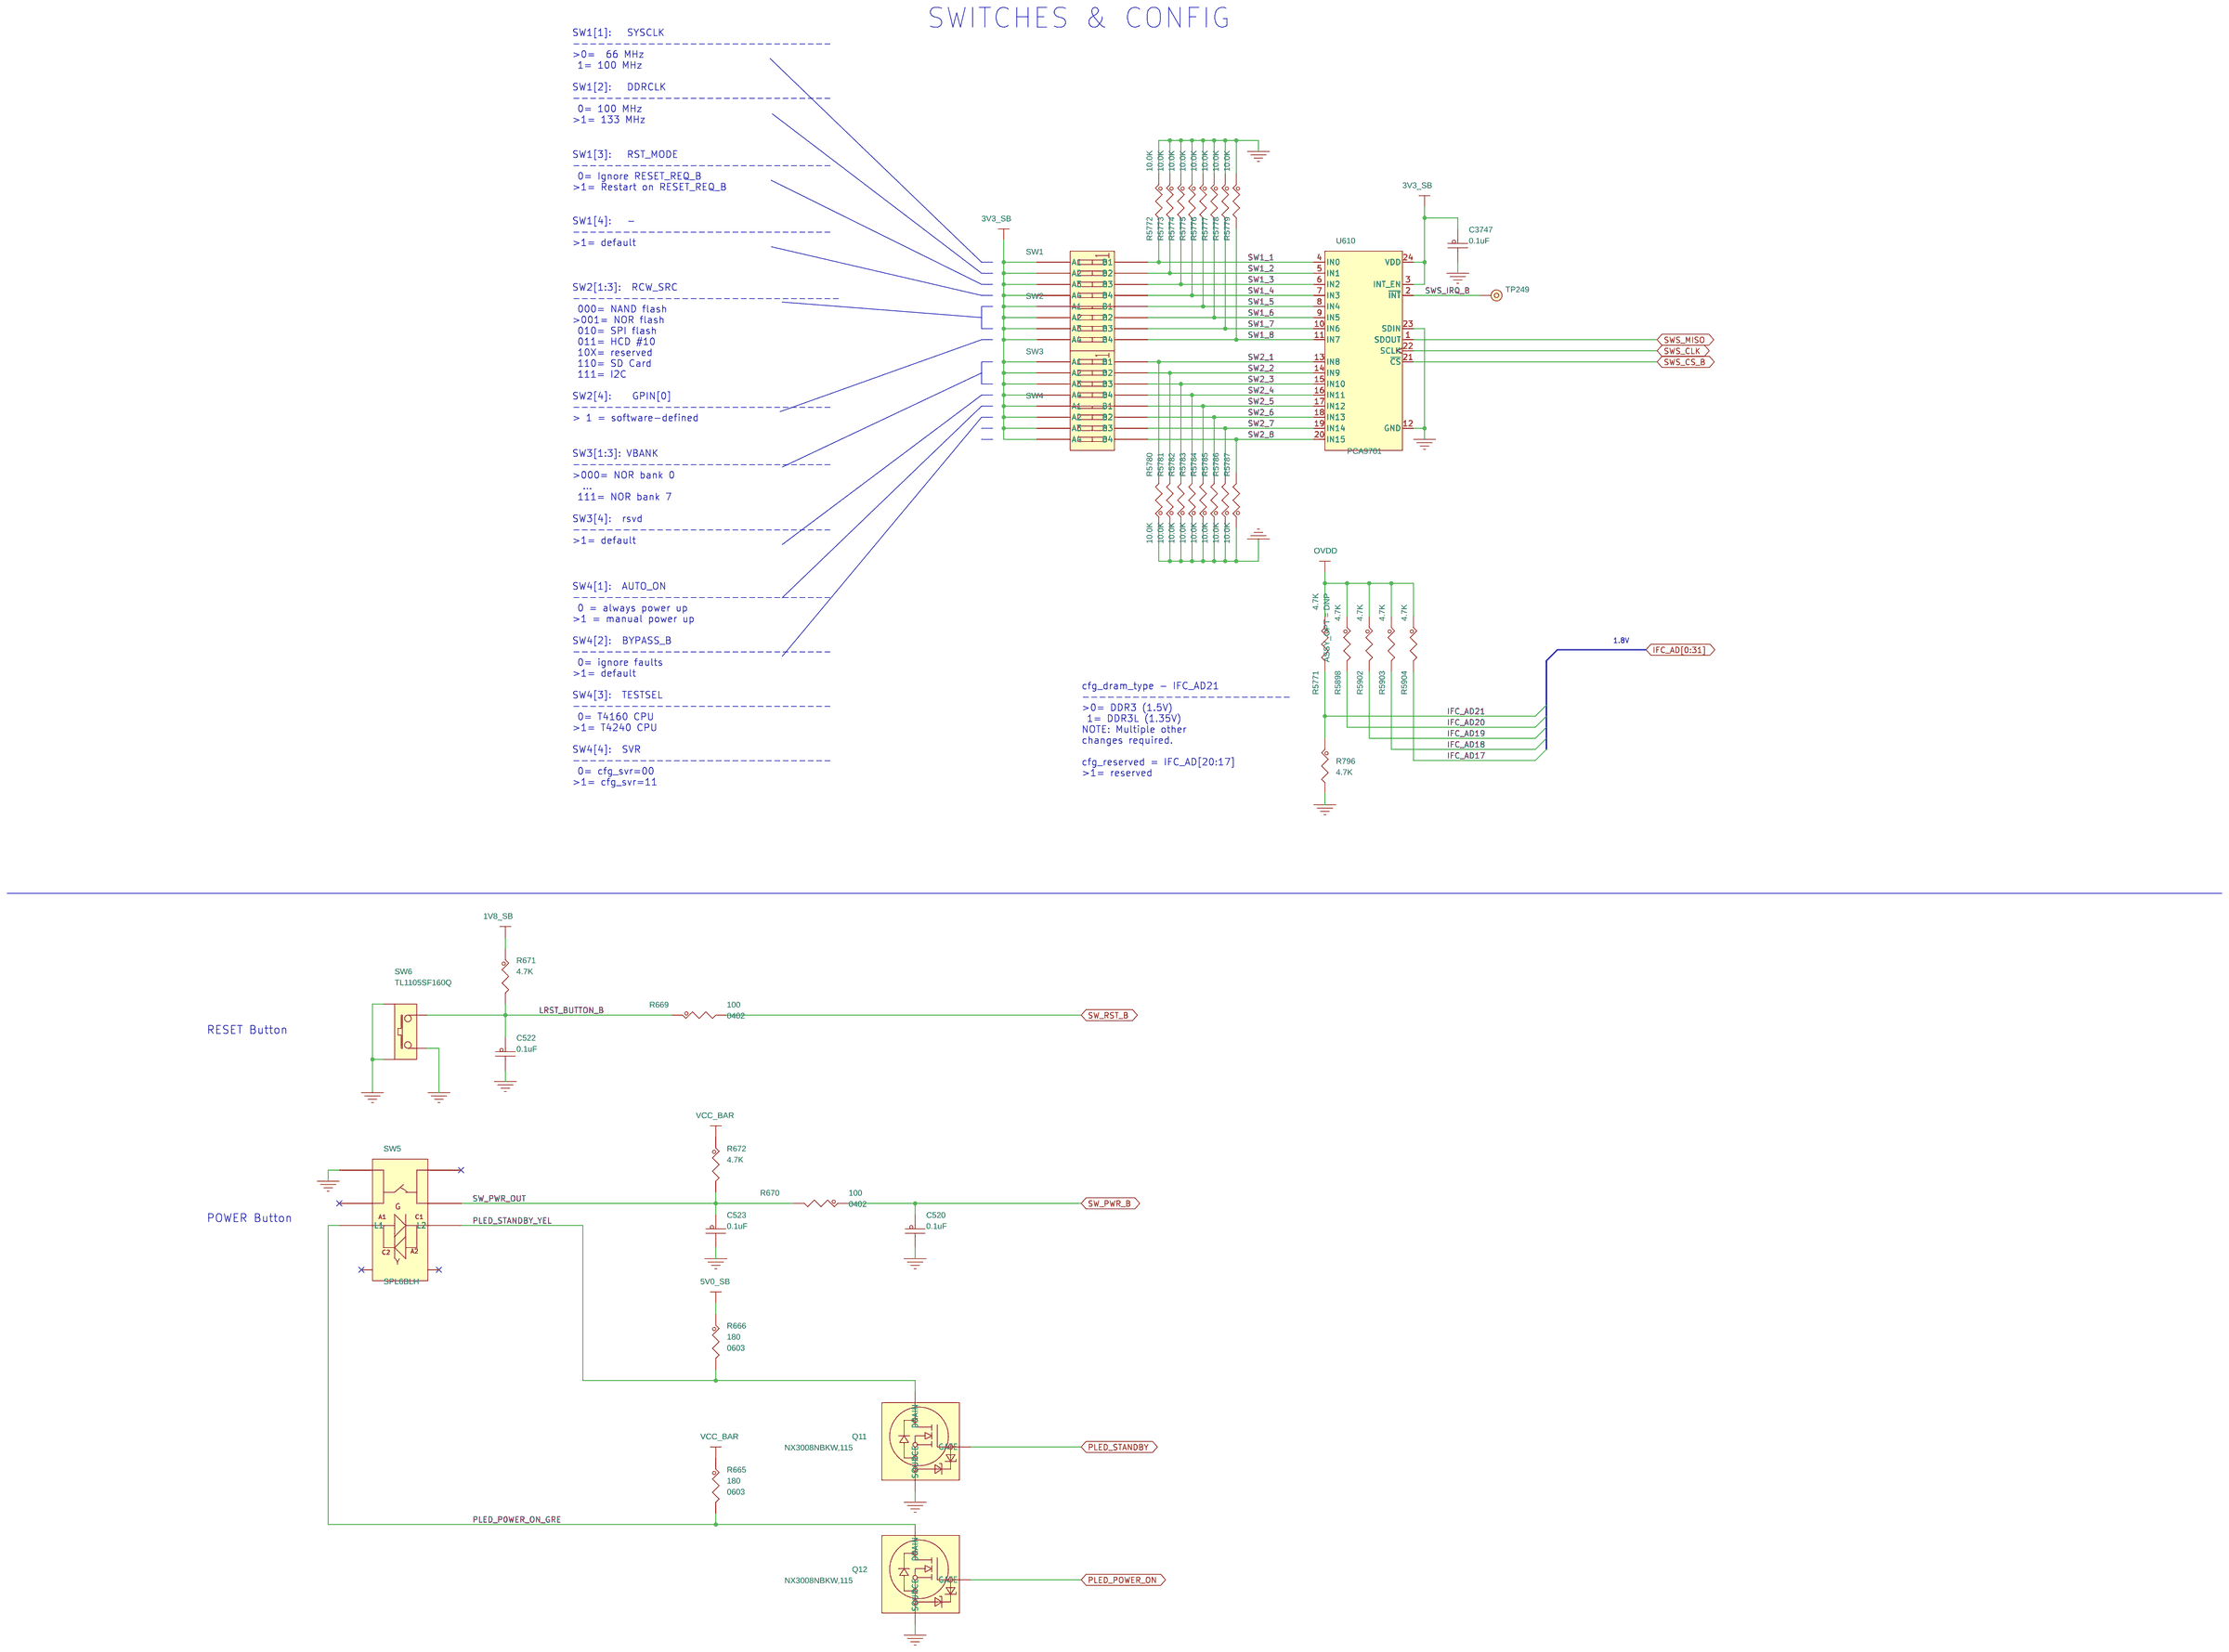
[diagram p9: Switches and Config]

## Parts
sheet Power Entry & Mechanical
C299  0.1uF  [CC0402_HD]
C5340  330uF  [cap_10p5_rad]
CT28  470uF  [cap_10p5_rad]
CT31  470uF  [cap_10p5_rad]
CT35  470uF  [cap_10p5_rad]
H1  MOUNTING HOLE  [mh315-158t_6p]
H2  MOUNTING HOLE  [mh315-158t_6p]
H3  MOUNTING HOLE  [mh315-158t_6p]
H4  MOUNTING HOLE  [mh315-158t_6p]
H5  MOUNTING HOLE  [mh315-158t_6p]
H6  MOUNTING HOLE  [mh315-158t_6p]
H7  MOUNTING HOLE  [mh315-158t_6p]
H8  MOUNTING HOLE  [mh315-158t_6p]
H9  MOUNTING HOLE  [mh315-158t_6p]
H10  MOUNTING HOLE  [mh315-158t_6p]
H11  MOUNTING HOLE  [mh315-158t_6p]
H12  MOUNTING HOLE  [mh315-158t_6p]
H13  MOUNTING HOLE  [mh315-158t_6p]
H14  MOUNTING HOLE  [mh315-158t_6p]
H15  MOUNTING HOLE  [mh315-158t_6p]
H16  MOUNTING HOLE  [mh315-158t_6p]
J8  CON 2X4  [conn_2x4_165_th]
J9  CON_2X12_PWR  [CON_ATXPWR_2X12_A]
Q13  NX3008NBKW,115  [sc70_3]
R337  4.7K  [RC0402_25]
R342  100  [RC0402_25]
R394  10.0K  [RC0402_25]
R748  100  [RC0402_25]
sheet Standby Power
C5116  1uF  [CC0402_HD]
C5117  1uF  [CC0402_HD]
C5118  1uF  [CC0402_HD]
C5119  1uF  [CC0402_HD]
C5120  1uF  [CC0402_HD]
C5121  1uF  [CC0402_HD]
R5727  4.7K  [RC0402_25]
R5728  4.7K  [RC0402_25]
R5729  4.7K  [RC0402_25]
U605  RT9013-33GQW  [dfn6_0p65_2x2_ep]
U606  RT9013-18GB  [SOT-23-5]
U607  RT9078-12GJ5_5P  [sot23-5]
sheet Switches and Config
C520  0.1uF  [CC0402_HD]
C522  0.1uF  [CC0402_HD]
C523  0.1uF  [CC0402_HD]
C3747  0.1uF  [CC0402_HD]
Q11  NX3008NBKW,115  [sc70_3]
Q12  NX3008NBKW,115  [sc70_3]
R665  180  [RC0402_25]
R666  180  [RC0402_25]
R669  100  [RC0402_25]
R670  100  [RC0402_25]
R671  4.7K  [RC0402_25]
R672  4.7K  [RC0402_25]
R796  4.7K  [RC0402_25]
R5771  4.7K  [RC0402_25]
R5772  10.0K  [RC0402_25]
R5773  10.0K  [RC0402_25]
R5774  10.0K  [RC0402_25]
R5775  10.0K  [RC0402_25]
R5776  10.0K  [RC0402_25]
R5777  10.0K  [RC0402_25]
R5778  10.0K  [RC0402_25]
R5779  10.0K  [RC0402_25]
R5780  10.0K  [RC0402_25]
R5781  10.0K  [RC0402_25]
R5782  10.0K  [RC0402_25]
R5783  10.0K  [RC0402_25]
R5784  10.0K  [RC0402_25]
R5785  10.0K  [RC0402_25]
R5786  10.0K  [RC0402_25]
R5787  10.0K  [RC0402_25]
R5898  4.7K  [RC0402_25]
R5902  4.7K  [RC0402_25]
R5903  4.7K  [RC0402_25]
R5904  4.7K  [RC0402_25]
SW1  416131160804  [sw4_dip_1p27_6p3x5p7]
SW2  416131160804  [sw4_dip_1p27_6p3x5p7]
SW3  416131160804  [sw4_dip_1p27_6p3x5p7]
SW4  416131160804  [sw4_dip_1p27_6p3x5p7]
SW5  SPL6BLH  [sw6_tact_led_th]
SW6  TL1105SF160Q  [sw2_tl1105s]
TP249  TPAD_020  [tpad_020_top]
U610  PCA9701  [tssop_24_0p65_8x4]
sheet System FPGA IO Ports
JP8  HDR 1X3  [hdr1x3_50mil_335h]
R5769  4.7K  [RC0402_25]
R5770  4.7K  [RC0402_25]
R5897  4.7K  [RC0402_25]
TP259  TPAD_020  [tpad_020_top]
TP290  TPAD_020  [tpad_020_top]
sheet System FPGA Power+Prog
C3690  27pF  [CC0402_25]
C3691  27pF  [CC0402_25]
C3697  22uF  [CC0805]
C3698  0.1uF  [CC0402_HD]
C3699  0.1uF  [CC0402_HD]
C3700  0.1uF  [CC0402_HD]
C3701  0.1uF  [CC0201]
C3702  0.1uF  [CC0201]
C3703  0.1uF  [CC0201]
C3710  0.1uF  [CC0201]
C3711  0.1uF  [CC0201]
C3712  0.1uF  [CC0201]
C3713  0.1uF  [CC0201]
C3714  0.1uF  [CC0201]
C3716  0.1uF  [CC0201]
C3717  0.1uF  [CC0201]
C3718  0.1uF  [CC0201]
C3719  0.1uF  [CC0201]
C3720  0.1uF  [CC0201]
C3721  0.1uF  [CC0201]
C3722  0.1uF  [CC0201]
C3723  0.1uF  [CC0201]
C3724  0.1uF  [CC0201]
C3725  0.1uF  [CC0201]
C3728  0.1uF  [CC0201]
C3729  0.1uF  [CC0201]
C3730  0.1uF  [CC0201]
C3731  0.1uF  [CC0201]
C3732  0.1uF  [CC0201]
C3733  0.1uF  [CC0201]
C3734  0.1uF  [CC0201]
C3735  0.1uF  [CC0201]
C3736  0.1uF  [CC0201]
C3737  0.1uF  [CC0201]
C3738  0.1uF  [CC0201]
C3739  0.1uF  [CC0201]
C3742  22uF  [CC0805]
C3743  22uF  [CC0805]
C3744  1uF  [CC0402_HD]
C3745  1uF  [CC0402_HD]
C3831  0.1uF  [CC0402_HD]
C3836  0.1uF  [CC0201]
C3837  0.1uF  [CC0201]
C3838  0.1uF  [CC0201]
C3839  0.1uF  [CC0201]
C3840  0.1uF  [CC0201]
C3841  0.1uF  [CC0201]
C3842  0.1uF  [CC0201]
C3843  0.1uF  [CC0201]
J69  HDR_1X5  [HDR105]
J105  HDR_2X5  [HDR205_HTST_SM]
JP7  HDR 1X3  [hdr1x3_50mil_335h]
R5582  1.0  [RC0805_OV]
R5583  1.0K  [RC0402_HD]
R5584  1.0K  [RC0402_HD]
R5585  1.0K  [RC0402_HD]
R5588  10.0K  [RC0402_25]
R5589  10.0K  [RC0402_25]
R5667  1.0K  [RC0402_HD]
R5671  1.0K  [RC0402_HD]
TP192  TPAD_020  [tpad_020_top]
TP193  TPAD_020  [tpad_020_top]
TP194  TPAD_020  [tpad_020_top]
TP195  TPAD_020  [tpad_020_top]
TP196  TPAD_020  [tpad_020_top]
TP197  TPAD_020  [tpad_020_top]
U27  M2GL005-VFG256  [bga256_0p8_14x14mm_c016s]  (sections A,B,C,D,E,F,G,H)
U250  SST25LF080  [so8-25x75-200]
Y19  16MHz  [xtal4_2p1x1p7]

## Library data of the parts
C299 C520 C522 C523 = CAP_NP: CAP CER 0.1uF 16V 10% X7R AEC-Q200 0402; AGILE_PN: 150-79025; CAD_APPROVED: Yes; FPLIST: CC0402_25,CC0402_HD,0402_CC,capc0402_l; HEIGHT: 0.55MM; MFG_NAME01: MURATA; MFG_PN01: GCM155R71C104KA55D; Package Size: 0402; Package Type: ø180mm Reel PAPER; ROHS: Yes; Rated Voltage: 16V; Temp Range: -55C to +125C; Tolerance: 10%
C5340 = CAP_POL: CAP ALEL 330uF 25V 20% -- RADIAL; AGILE_PN: 150-78978; CAD_APPROVED: Yes; ESR: 0.014 OHMS; HEIGHT: 13 MM; MFG_NAME01: PANASONIC; MFG_PN01: 25SEPF330M; ROHS: Yes; ROOM: VDD_GVDD_PS; Rated Voltage: 25V; Temp Range: -55C to +150C; Temp_Range: –55 °C to +105 °C; Tolerance: 20%; VOLTAGE: 25V
CT28 CT31 CT35 = CAP_POL: CAP ALEL 470uF 16V 20% -- RADIAL; AGILE_PN: 150-79116; CAD_APPROVED: Yes; HEIGHT: 14MM; MFG_NAME01: RUBYCON CORPORATION; MFG_PN01: 16YXF470M10X12.5; Package Size: 10X12.5X14MM; ROHS: Yes; Rated Voltage: 16V; Tolerance: 20%
H1-H16 = MOUNTING_HOLE_ATX_6P: MOUNTING HOLE DRILL 158 PAD 315 VIAX6(PAD-40 DRILL-20) NO PART TO ORDER; AGILE_PN: 280-76944; CAD_APPROVED: Yes; HEIGHT: 0.127MM; ROHS: Yes
J8 = ATX_12V_PWR_CONN8: CON 2X4 PLUG SHRD TH WITH PEGS 4.2MM SP 515H SN 140L; 3D_Mechanical_Footprint_File: http://fcl.am.freescale.net/ALLEGRO/step/CONN_2X4_165_TH.STEP; AGILE_PN: 210-80068; CAD_APPROVED: Yes; HEIGHT: 13.08MM; MFG_NAME01: MOLEX; MFG_PN01: 39-29-9082; Package Type: CON; ROHS: Yes; ROOM: ATX_POWER; SILK: ATX PS 12
J9 = CONN_PWR_12X2: CON 2X12 PWR PLUG SHRD TH WITH PEGS 165MIL CTR 504H SN 138L; 3D_Mechanical_Footprint_File: http://fcl.am.freescale.net/ALLEGRO/step/con_atxpwr_2x12_a.STEP; AGILE_PN: 210-77813; CAD_APPROVED: Yes; HEIGHT: 12.8 MM; MFG_NAME01: MOLEX; MFG_PN01: 44206-0001; ROHS: Yes
Q11-Q13 = NMOS_NX3008NBK: TRAN NMOS SW 30V 350mA AEC-Q101 SC-70; 3D_Mechanical_Footprint_File: http://fcl.am.freescale.net/ALLEGRO/step/sc70_3.STEP; AGILE_PN: 480-79736; CAD_APPROVED: Yes; HEIGHT: 1.1MM; MFG_NAME01: NEXPERIA; ROHS: Yes
R337 R671 R672 R796 R5727-R5729 R5769 R5770 R5897 R5898 R5902-R5904 = RES: RES MF 4.7K 1/10W 5% AEC-Q200 0402; AGILE_PN: 470-82064; CAD_APPROVED: Yes; FPLIST: RC0402_25,RC0402_HD,0402_CC,RC0402_X2; HEIGHT: 0.41mm; MFG_NAME01: KOA SPEER; MFG_PN01: RK73B1ETTP472J; ROHS: Yes; Temp Range: -55C to +155C; Tolerance: 5%
R342 R669 R670 = RES: RES MF 100 OHM 1/16W 1% AEC-Q200 0402; AGILE_PN: 470-80666; CAD_APPROVED: Yes; FPLIST: RC0402_25,RC0402_HD,0402_CC; HEIGHT: 0.4 MM; MFG_NAME01: KOA SPEER; MFG_PN01: RK73H1ETTP1000F; Package: 0402; Part Number: 4RC1001B11X00; Product Name: (H)RES 100E 1/16W 0402 1% PBFREE; ROHS: Yes
R394 R5772-R5787 = RES: RES MF 10.0K 1/16W 1% AEC-Q200 0402; AGILE_PN: 470-75416; CAD_APPROVED: Yes; FPLIST: RC0402_25,RC0402_HD,0402_CC; HEIGHT: 0.4MM; MFG_NAME01: KOA SPEER; MFG_PN01: RK73H1ETTP1002F; Package: 0402; Part Number: 4RC1003B11X00; Product Name: (H)RES 10K 1/16W 0402 1% PBFREE; ROHS: Yes; Temp Range: –55 °C to +155 °C; Tolerance: 1%
R748 = RES: RES MF 100 OHM 1/16W 1% AEC-Q200 0402; AGILE_PN: 470-80666; ASSY_OPT: DNP; CAD_APPROVED: Yes; FPLIST: RC0402_25,RC0402_HD,0402_CC; HEIGHT: 0.4 MM; MFG_NAME01: KOA SPEER; MFG_PN01: RK73H1ETTP1000F; Package: 0402; Part Number: 4RC1001B11X00; Product Name: (H)RES 100E 1/16W 0402 1% PBFREE; ROHS: Yes
C5116-C5121 = CAP_NP: CAP CER 1uF 10V 10% X7S 0402; AGILE_PN: 150-80357; CAD_APPROVED: Yes; FPLIST: CC0402_25,CC0402_HD,0402_CC,capc0402_l; HEIGHT: 0.6MM; MFG_NAME01: MURATA; MFG_PN01: GRM155C71A105KE11D; Package: 0402; Package Size: 0402; Part Number: 4CC105B101X00; Product Name: (H)MLCC 1uF/10V +-10% 0402 X5R; ROHS: Yes; Rated Voltage: 10V; Temp Range: -55C to +125C; Tolerance: 10%
U605 = RT9013_DFN6_EP: IC VREG LDO 3.3V 500MA 2.2-5.5V DFN6; 3D_Mechanical_Footprint_File: http://fcl.am.freescale.net/ALLEGRO/step/dfn6_0p65_2x2_ep.STEP; AGILE_PN: 315-80908; CAD_APPROVED: Yes; HEIGHT: 0.8MM; MFG_NAME01: RICHTEK; ROHS: Yes; VOLTAGE: 2.2-5.5V
U606 = NCP561: IC VREG LDO 1.8V 500MA 2.2-5.5V SOT-23-5; AGILE_PN: 315-82151; CAD_APPROVED: Yes; HEIGHT: 1.295MM; MFG_NAME01: RICHTEK; ROHS: Yes; Temp Range: -40°C to + 85°C; VOLTAGE: 2.2-5.5V
U607 = RT9078-12GJ5_5p: IC VREG  LDO 1.2V 300mA  1.2 - 5.5V  TSOT23-5; AGILE_PN: 315-82324; CAD_APPROVED: Yes; HEIGHT: 0.4MM; MFG_NAME01: RICHTEK; MFG_PN01: RT9078-12GJ5; ROHS: Yes; VOLTAGE: 1.2 - 5.5V
C3747 = CAP_NP: CAP CER 0.1uF 16V 10% X7R AEC-Q200 0402; AGILE_PN: 150-79025; CAD_APPROVED: Yes; FPLIST: CC0402_25,CC0402_HD,0402_CC,capc0402_l; HEIGHT: 0.55MM; MFG_NAME01: MURATA; MFG_PN01: GCM155R71C104KA55D; PRIORITY_PN: 021-00389; Package Size: 0402; Package Type: ø180mm Reel PAPER; ROHS: Yes; ROOM: SWITCHES; Rated Voltage: 16V; Temp Range: -55C to +125C; Tolerance: 10%; VOLTAGE: 35V
R665 R666 = RES: RES MF 180 OHM 1/10W 1% AEC-Q200 0402; AGILE_PN: 470-81529; CAD_APPROVED: Yes; FPLIST: RC0402_25,RC0402_HD,0402_CC; HEIGHT: 0.40 MM; MFG_NAME01: KOA SPEER; MFG_PN01: RK73H1ETTP1800F; Package: 0603; Part Number: 4RC1801C51X00; Product Name: (H)RES 180E 1/10W 0603 5% PBFREE; ROHS: Yes; Temp Range: -55°C to +155°C; Tolerance: 1%
R5771 = RES: RES MF 4.7K 1/10W 5% AEC-Q200 0402; AGILE_PN: 470-82064; ASSY_OPT: DNP; CAD_APPROVED: Yes; FPLIST: RC0402_25,RC0402_HD,0402_CC,RC0402_X2; HEIGHT: 0.41mm; MFG_NAME01: KOA SPEER; MFG_PN01: RK73B1ETTP472J; ROHS: Yes; Temp Range: -55C to +155C; Tolerance: 5%
SW1-SW4 = SW_DIP4: SW DIP 4 POS 0.025A@24VDC SMT; 3D_Mechanical_Footprint_File: http://fcl.am.freescale.net/ALLEGRO/step/sw4_dip_1p27_6p3x5p7.pdf; AGILE_PN: 510-78047; CAD_APPROVED: Yes; HEIGHT: 2.1MM; MFG_NAME01: WURTH ELEKTRONIK EISOS GMBH & CO. KG (ELECTRONIC & ELECTROMEHANICAL COMP); ROHS: Yes
SW5 = SPL6BL_SW6_TACT: SW SPST TACT NO RA YEL/GRN 50MA 12V TH; AGILE_PN: 510-78034; CAD_APPROVED: Yes; HEIGHT: 7.75MM; MFG_NAME01: SALECOM ELECTRONICS CO., LTD; MFG_PN01: SPL6BL-2-56-S-9-B-H; ROHS: Yes
SW6 = SW_TACT-SPST-2_SM1: SW SPST TACT NO RA 50MA 12V TH; 3D_Mechanical_Footprint_File: http://fcl.am.freescale.net/ALLEGRO/step/sw2_tl1105s.STEP; AGILE_PN: 510-77922; CAD_APPROVED: Yes; HEIGHT: 7.25 MM; MFG_NAME01: E SWITCH; ROHS: Yes
TP192-TP197 TP249 TP259 TP290 = T_POINT_TH: TEST POINT PAD 20 MILS SMT, NOT PART TO ORDER; AGILE_PN: 211-81036; CAD_APPROVED: Yes; FPLIST: tpad_020_top,tpad_020_btm_nsp; HEIGHT: 0.127MM; MFG_NAME01: NO PART ORDER; MFG_PN01: NA; ROHS: Yes
U610 = PCA9701PW_24: IC REG SHIFT 16-BIT SPI GPI 2.5V-5.5V TSSOP24; 3D_Mechanical_Footprint_File: http://fcl.am.freescale.net/ALLEGRO/step/tssop_24_0p65_8x4.STEP; AGILE_PN: 312-80698; CAD_APPROVED: Yes; HEIGHT: 1.1MM; MFG_NAME01: NXP SEMICONDUCTORS; MFG_PN01: PCA9701PW,118; ROHS: Yes; ROOM: SWITCHES; VOLTAGE: 2.5V-5.5V
JP8 = CONN_HDR_3X1: HDR 1X3 TH 1.27MM SP 335H AU 120L; 3D_Mechanical_Footprint_File: http://fcl.am.freescale.net/ALLEGRO/step/hdr1x3_50mil_335h.STEP; AGILE_PN: 210-83335; ASSY_OPT: DNP; CAD_APPROVED: Yes; HEIGHT: 8.509MM; MFG_NAME01: SAMTEC; MFG_PN01: TMS-103-01-L-S; Package Type: PCB, Through Hole; ROHS: Yes; SILK: FPGA; Temp Range: -55°C to 125°C
C3690 C3691 = CAP_NP: CAP CER 27pF 50V 5% C0G AEC-Q200 0402; AGILE_PN: 150-80448; CAD_APPROVED: Yes; FPLIST: CC0402_25,CC0402_HD,0402_CC; HEIGHT: 0.55MM; MFG_NAME01: MURATA; MFG_PN01: GCM1555C1H270JA16D; Package Size: 0402; Package Type: SMD; ROHS: Yes; Rated Voltage: 50V; Temp Range: -55C to +125C; Tolerance: 5%; VOLTAGE: 50V
C3697 C3742 C3743 = CAP_NP: CAP CER 22uF 25V 20% X5R 0805; AGILE_PN: 150-79304; CAD_APPROVED: Yes; FPLIST: CC0805_OV,CC0805,0805_CC; HEIGHT: 1.45MM; MFG_NAME01: MURATA; MFG_PN01: GRM21BR61E226ME44; PRIORITY_PN: 021-00377; Package Size: 0805; Package Type: SMD; ROHS: Yes; ROOM: GVDD_PS; Rated Voltage: 25V; Temp Range: -55C to +85C; Tolerance: 20%; VOLTAGE: 25V
C3698-C3700 C3831 = CAP_NP: CAP CER 0.1uF 16V 10% X7R AEC-Q200 0402; AGILE_PN: 150-79025; CAD_APPROVED: Yes; FPLIST: CC0402_25,CC0402_HD,0402_CC,capc0402_l; HEIGHT: 0.55MM; MFG_NAME01: MURATA; MFG_PN01: GCM155R71C104KA55D; PRIORITY_PN: 021-00389; Package Size: 0402; Package Type: ø180mm Reel PAPER; ROHS: Yes; ROOM: 1V5_SB; Rated Voltage: 16V; Temp Range: -55C to +125C; Tolerance: 10%; VOLTAGE: 35V
C3701-C3703 C3710-C3714 C3716-C3725 C3728-C3739 C3836-C3843 = CAP_NP: CAP CER 0.1uF 16V 20% X7R 0201; AGILE_PN: 150-79872; CAD_APPROVED: Yes; FPLIST: CC0201,CC0201_HD,0201_CC,RC0201_RF; HEIGHT: 0.33MM; MFG_NAME01: MURATA; MFG_PN01: GRM033Z71C104ME14; PRIORITY_PN: 021-00389; Package Size: 0201; ROHS: Yes; ROOM: 1V5_SB; Rated Voltage: 16V; Temp Range: -55C to +125C; Tolerance: 20%; VOLTAGE: 35V
C3744 C3745 = CAP_NP: CAP CER 1uF 10V 10% X7S 0402; AGILE_PN: 150-80357; CAD_APPROVED: Yes; FPLIST: CC0402_25,CC0402_HD,0402_CC,capc0402_l; HEIGHT: 0.6MM; MFG_NAME01: MURATA; MFG_PN01: GRM155C71A105KE11D; Package Size: 0402; ROHS: Yes; Rated Voltage: 10V; SIGNAL_MODEL: DEFAULT_CAPACITOR_1e+06pF_2_1; Temp Range: -55C to +125C; Tolerance: 10%; VOLTAGE: 10V
J69 = CONN_HDR_5X1: HDR 1X5 TH 100MIL SP 372H SN 114L; 3D_Mechanical_Footprint_File: http://fcl.am.freescale.net/ALLEGRO/step/hdr105_382h.STEP; AGILE_PN: 210-80654; ASSY_OPT: DNP; CAD_APPROVED: Yes; HEIGHT: 9.45MM; MFG_NAME01: MOLEX; MFG_PN01: 90120-0125; ROHS: Yes; SILK: FSPI_PRG; Temp Range: -55°C to +125°C
J105 = HTST-105-01-S-DV: HDR 2X5 SMT 100MIL CTR 400H AU; 3D_Mechanical_Footprint_File: http://fcl.am.freescale.net/ALLEGRO/step/hdr205_htst_sm.STEP; AGILE_PN: 211-75193; CAD_APPROVED: Yes; HEIGHT: 10.16MM; MFG_NAME01: SAMTEC; MFG_PN01: HTST-105-01-SM-DV; PRIORITY_PN: 028-00575; ROHS: Yes; ROOM: FPGA; SILK: FPGA PROG
JP7 = CONN_HDR_3X1: HDR 1X3 TH 1.27MM SP 335H AU 120L; 3D_Mechanical_Footprint_File: http://fcl.am.freescale.net/ALLEGRO/step/hdr1x3_50mil_335h.STEP; AGILE_PN: 210-83335; ASSY_OPT: DNP; CAD_APPROVED: Yes; HEIGHT: 8.509MM; MFG_NAME01: SAMTEC; MFG_PN01: TMS-103-01-L-S; Package Type: PCB, Through Hole; ROHS: Yes; SILK: FPGARST; Temp Range: -55°C to 125°C
R5582 = RES: RES MF 1.0 OHM 1/8W 1% 0805; AGILE_PN: 470-76317; CAD_APPROVED: Yes; FPLIST: RC0805_OV,RC0805,0805_CC; HEIGHT: 0.6MM; MFG_NAME01: YAGEO AMERICA; MFG_PN01: RC0805FR-071RL; ROHS: Yes; ROOM: VDD_GVDD_PS; SIGNAL_MODEL: DEFAULT_RESISTOR_1OHM_2_1; Tolerance: 1%; VOLTAGE: 1/8W
R5583-R5585 R5667 R5671 = RES: RES MF 1.0K 1/16W 1% 0402; AGILE_PN: 470-76037; CAD_APPROVED: Yes; FPLIST: RC0402_25,RC0402_HD,RC0402_X2,0402_CC; HEIGHT: 0.4MM; MFG_NAME01: YAGEO AMERICA; MFG_PN01: RC0402FR-071KL; PRIORITY_PN: 006-00553; ROHS: Yes; ROOM: VDD_GVDD_PS; SIGNAL_MODEL: DEFAULT_RESISTOR_1000OHM_2_1; TOL: 5%; Tolerance: 1%; VOLTAGE: 1/16W
R5588 R5589 = RES: RES MF 10.0K 1/16W 1% AEC-Q200 0402; AGILE_PN: 470-75416; CAD_APPROVED: Yes; FPLIST: RC0402_25,RC0402_HD,0402_CC; HEIGHT: 0.4MM; MFG_NAME01: KOA SPEER; MFG_PN01: RK73H1ETTP1002F; PRIORITY_PN: 006-00552; ROHS: Yes; ROOM: FPGA; SIGNAL_MODEL: DEFAULT_RESISTOR_10000OHM_2_1; TOL: 1%; Temp Range: –55 °C to +155 °C; Tolerance: 1%
U27 = M2GL005_VFG256: IC FPGA IGLOO2 FLASH 6060LEs 128KB NVM 703Kb SRAM 1.2V-3.3V VF256; 3D_Mechanical_Footprint_File: http://fcl.am.freescale.net/ALLEGRO/step/bga256_0p8_14x14mm_c016s.STEP; AGILE_PN: 312-82920; CAD_APPROVED: Yes; HEIGHT: 1.56MM; MFG_NAME01: MICROSEMI; MFG_PN01: M2GL005-VFG256I; ROHS: Yes; Temp Range: -40°C ~ 100°C; VOLTAGE: 1.2V-3.3V
U250 = SST25LF080A: IC MEM SPI SERIAL FLASH 8MBIT 50MHZ 2.7-3.6V SO8; AGILE_PN: 334-75192; ASSY_OPT: DNP; CAD_APPROVED: YES; HEIGHT: 2.16MM; MFG_NAME01: SST; MFG_PN01: SST25VF080B-50-4C-S2AF; ROHS: Yes
Y19 = XTAL_13: XTAL 16.0000MHZ 8PF SMD; AGILE_PN: 230-78411; CAD_APPROVED: Yes; Frequency Tolerance: 25ppm; HEIGHT: 0.45mm; MFG_NAME01: KYOCERA; MFG_PN01: CX2016DB16000D0WZRC1; Package Size: 0.079" L x 0.063" W (2.00mm x 1.60mm); ROHS: Yes; Temp Range: -25°C ~ 75°C

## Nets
1V2_SB: C3725.1 C3728.1 C3729.1 C3730.1 C3731.1 C3732.1 C3733.1 C3734.1 C3735.1 C3736.1 C3737.1 C3738.1 C3739.1 C3742.1 C3744.1 C5121.1 U27.F7(VDD1) U27.F9(VDD2) U27.G6(VDD4) U27.G8(VDD5) U27.G10(VDD3) U27.H7(VDD6) U27.H9(VDD7) U27.J8(VDD9) U27.J10(VDD8) U27.K7(VDD10) U27.K9(VDD11) U27.L8(VDD12) U607.5(VOUT)
1V2SB_EN: R5729.2 U607.3(EN)
1V8_SB: C3836.1 C3837.1 C3838.1 C3839.1 C3840.1 C3841.1 C3842.1 C3843.1 C5118.1 R671.1 U27.A11(VDDI0_1) U27.B14(VDDI0_2) U27.C7(VDDI0_3) U27.D10(VDDI0_4) U27.H2(VDDI5_1) U27.J6(VDDI5_2) U27.L1(VDDI4_1) U27.L6(VDDI4_3) U27.L10(VDDI4_2) U27.M4(VDDI4_4) U27.N7(VDDI4_5) U27.P10(VDDI4_6) U27.R3(VDDI4_8) U27.R13(VDDI4_7) U27.T6(VDDI4_9) U606.5(VOUT)
1V8SB_EN: R5728.2 U606.3(ENABLE)
3V3_SB: C3699.1 C3700.1 C3701.1 C3702.1 C3703.1 C3710.1 C3711.1 C3712.1 C3713.1 C3714.1 C3716.1 C3717.1 C3718.1 C3719.1 C3720.1 C3721.1 C3722.1 C3723.1 C3724.1 C3743.1 C3745.1 C3747.1 C5117.1 C5120.1 J105.6 J105.7 R672.1 R5582.1 R5583.1 R5588.1 R5589.1 R5667.1 R5671.1 R5729.1 SW1.1(A1) SW1.2(A2) SW1.3(A3) SW1.4(A4) SW2.1(A1) SW2.2(A2) SW2.3(A3) SW2.4(A4) SW3.1(A1) SW3.2(A2) SW3.3(A3) SW3.4(A4) SW4.1(A1) SW4.2(A2) SW4.3(A3) SW4.4(A4) U27.A1(VDDI6_1) U27.B4(VDDI6_2) U27.E3(VDDI6_3) U27.E13(VDDI1_1) U27.F6(VDDI6_4) U27.F16(VDDI2_1) U27.G11(VPP1) U27.H11(VPPNVM) U27.H12(VDDI2_2) U27.J15(VDDI2_3) U27.K5(VPP3) U27.K11(VPP2) U27.L12(VDDI3_1) U27.M14(VDDI2_4) U27.T15(VPP4) U27.T16(VPP5) U250.8(VDD) U605.4(VOUT) U607.1(VIN) U610.3(INT_EN) U610.24(VDD) ; also on sheet 47 48 51 54
3V3SB_EN: R5727.2 U605.1(EN)
5V0_SB: C5116.1 C5119.1 CT31.1 J9.9(VSTDBY) R394.2 R665.1 R666.1 R5727.1 R5728.1 U605.3(VIN) U606.1(VIN)
GND: C299.2 C520.2 C522.2 C523.2 C3690.2 C3691.2 C3699.2 C3700.2 C3701.2 C3702.2 C3703.2 C3710.2 C3711.2 C3712.2 C3713.2 C3714.2 C3716.2 C3717.2 C3718.2 C3719.2 C3720.2 C3721.2 C3722.2 C3723.2 C3724.2 C3725.2 C3728.2 C3729.2 C3730.2 C3731.2 C3732.2 C3733.2 C3734.2 C3735.2 C3736.2 C3737.2 C3738.2 C3739.2 C3742.2 C3743.2 C3744.2 C3745.2 C3747.2 C3831.2 C3836.2 C3837.2 C3838.2 C3839.2 C3840.2 C3841.2 C3842.2 C3843.2 C5116.2 C5117.2 C5118.2 C5119.2 C5120.2 C5121.2 C5340.2 CT28.2 CT31.2 CT35.2 H1.1(GND1) H1.2(GND2) H1.3(GND3) H1.4(GND4) H1.5(GND5) H1.6(GND6) H1.7(GND7) H2.1(GND1) H2.2(GND2) H2.3(GND3) H2.4(GND4) H2.5(GND5) H2.6(GND6) H2.7(GND7) H3.1(GND1) H3.2(GND2) H3.3(GND3) H3.4(GND4) H3.5(GND5) H3.6(GND6) H3.7(GND7) H4.1(GND1) H4.2(GND2) H4.3(GND3) H4.4(GND4) H4.5(GND5) H4.6(GND6) H4.7(GND7) H5.1(GND1) H5.2(GND2) H5.3(GND3) H5.4(GND4) H5.5(GND5) H5.6(GND6) H5.7(GND7) H6.1(GND1) H6.2(GND2) H6.3(GND3) H6.4(GND4) H6.5(GND5) H6.6(GND6) H6.7(GND7) H7.1(GND1) H7.2(GND2) H7.3(GND3) H7.4(GND4) H7.5(GND5) H7.6(GND6) H7.7(GND7) H8.1(GND1) H8.2(GND2) H8.3(GND3) H8.4(GND4) H8.5(GND5) H8.6(GND6) H8.7(GND7) H9.1(GND1) H9.2(GND2) H9.3(GND3) H9.4(GND4) H9.5(GND5) H9.6(GND6) H9.7(GND7) H10.1(GND1) H10.2(GND2) H10.3(GND3) H10.4(GND4) H10.5(GND5) H10.6(GND6) H10.7(GND7) H11.1(GND1) H11.2(GND2) H11.3(GND3) H11.4(GND4) H11.5(GND5) H11.6(GND6) H11.7(GND7) H12.1(GND1) H12.2(GND2) H12.3(GND3) H12.4(GND4) H12.5(GND5) H12.6(GND6) H12.7(GND7) H13.1(GND1) H13.2(GND2) H13.3(GND3) H13.4(GND4) H13.5(GND5) H13.6(GND6) H13.7(GND7) H14.1(GND1) H14.2(GND2) H14.3(GND3) H14.4(GND4) H14.5(GND5) H14.6(GND6) H14.7(GND7) H15.1(GND1) H15.2(GND2) H15.3(GND3) H15.4(GND4) H15.5(GND5) H15.6(GND6) H15.7(GND7) H16.1(GND1) H16.2(GND2) H16.3(GND3) H16.4(GND4) H16.5(GND5) H16.6(GND6) H16.7(GND7) J8.1(GND1) J8.2(GND2) J8.3(GND3) J8.4(GND4) J9.3(GND_P3) J9.5(GND_P5) J9.7(GND_P7) J9.15(GND_P15) J9.17(GND_P17) J9.18(GND_P18) J9.19(GND_P19) J9.24(GND_P24) J69.5 J105.2 J105.10 JP7.2 Q11.2(SOURCE) Q12.2(SOURCE) Q13.2(SOURCE) R748.2 R796.2 R5584.2 R5585.2 R5769.2 R5770.2 R5772.1 R5773.1 R5774.1 R5775.1 R5776.1 R5777.1 R5778.1 R5779.1 R5780.1 R5781.1 R5782.1 R5783.1 R5784.1 R5785.1 R5786.1 R5787.1 R5897.2 SW5.1 SW6.2 SW6.3 SW6.4 U27.A6(VSS2) U27.A16(VSS1) U27.B9(VSS3) U27.C2(VSS5) U27.C12(VSS4) U27.D5(VSS7) U27.D15(VSS6) U27.F1(VSS8) U27.F8(VSS10) U27.F10(VSS9) U27.G4(VSS12) U27.G7(VSS13) U27.G9(VSS14) U27.G14(VSS11) U27.H6(VSS16) U27.H8(VSS17) U27.H10(VSS15) U27.J7(VSS18) U27.J9(VSS19) U27.J11(VSSNVM) U27.K3(VSS22) U27.K6(VSS23) U27.K8(VSS24) U27.K10(VSS20) U27.K13(VSS21) U27.L7(VSS26) U27.L9(VSS27) U27.L16(VSS25) U27.N2(VSS29) U27.N12(VSS28) U27.P5(VSS31) U27.P15(VSS30) U27.R8(VSS32) U27.T1(VSS33) U27.T11(VSS34) U250.4(VSS) U605.2(GND1) U605.7(GND2) U606.2(GND) U607.2(GND) U610.12(GND) U610.23(SDIN) Y19.2 Y19.4 ; also on sheet 11 12 13 14 15 16 18 19 20 21 22 24 25 27 28 29 30 31 32 33 34 35 36 37 38 39 40 41 42 43 44 45 46 47 48 49 50 51 52 53 54
VCC_3.3: CT35.1 J9.1(+3.3V_P1) J9.2(+3.3V_P2) J9.12(+3.3V_P12) J9.13(+3.3V_P13) R337.1 ; also on sheet 12 13 16 18 24 25 31 32 33 36 39 40 41 42 43 44 47 48 49 50 51 53
VCC_5: CT28.1 J9.4(VCC_P4) J9.6(VCC_P6) J9.21(VCC_P21) J9.22(VCC_P22) J9.23(VCC_P23) ; also on sheet 12 49
VCC_12: C5340.1 J9.10(+12V_P10) J9.11(+12V_P11) ; also on sheet 11 14 15 47 48 53
VCC_12_8P: J8.5(12V_1) J8.6(12V_2) J8.7(12V_3) J8.8(12V_4) ; also on sheet 12
VDD_ALERT_B: U27.M15(MSIO1PB2) ; also on sheet 12
ALT_RST_B: C3831.1 JP7.1 R5671.2 U27.L11(DEVRST_N)
ASLEEP: U27.B13(DDRIO25PB0) ; also on sheet 27
ATX_PWROK: R342.2 U27.L15(MSIO0NB2)
ATXPWRGD: C299.1 J9.8(PWRGOOD) R337.2 R342.1
CFG_DDRCLK: U27.M1(MSIO86PB4) ; also on sheet 25
CFG_SYSCLK: U27.P3(MSIO85NB4) ; also on sheet 25
CFG_TESTSEL_B: U27.J3(MSIOD71PB5) ; also on sheet 27
CFG_VBANK0: U27.T8(MSIO98NB4) ; also on sheet 34
CFG_VBANK1: U27.T7(MSIO98PB4) ; also on sheet 34
CFG_VBANK2: U27.T2(MSIO97NB4) ; also on sheet 34
COP_HRST_B: U27.K1(MSIOD72PB5) ; also on sheet 27
COP_SRST_B: U27.K2(MSIOD72NB5) ; also on sheet 27
COP_TRST_B: U27.H3(MSIOD71NB5) ; also on sheet 27
DUT_HRESET_B: U27.H5(MSIOD70PB5/CCC_NE1_CLKI1) ; also on sheet 27
DUT_PORESET_B: U27.H1(MSIOD69PB5/CCC_NE1_CLKI2) ; also on sheet 27
DUT_RESET_REQ_B: U27.G1(MSIOD69NB5) ; also on sheet 27
DUT_TRST_B: U27.H4(MSIOD70NB5) ; also on sheet 27
FPGA_EXTAL: C3691.1 U27.R16(XTLOSC_MAIN_EXTAL) Y19.1
FPGA_JTSEL: R5583.2 U27.N13(JTAGSEL)
FPGA_PLL: C3697.1 C3698.1 R5582.2 U27.E10(CCC_NE0_NE1_HPMS_MDDR_PLL_VDDA)
FPGA_PRB: JP7.3 U27.C14(MSIO15NB1)
FPGA_TCK: J105.1 R5585.1 U27.P14(JTAG_TCK)
FPGA_TDI: J105.9 U27.N16(JTAG_TDI)
FPGA_TDO: J105.3 U27.N14(JTAG_TDO)
FPGA_TMS: J105.5 U27.P16(JTAG_TMS)
FPGA_TRST_B: J105.8 R5584.1 U27.N15(JTAG_TRSTB)
FPGA_XTAL: C3690.1 U27.R15(XTLOSC_MAIN_XTAL) Y19.3
FPGAUPD_SCK: J69.2 U27.F15(MSIO12PB2/SPI_0_CLK) U250.6(SCK)
FPGAUPD_SCS_B: J69.1 U27.D16(MSIO13NB2/SPI_0_SS0) U250.1(CE#)
FPGAUPD_SDI: J69.3 U27.F14(MSIO12NB2/SPI_0_SDI) U250.2(SO)
FPGAUPD_SDO: J69.4 U27.E16(MSIO13PB2/SPI_0_SDO) U250.5(SI)
FUPD_B: R5667.2 TP197.1(TP) U27.E12(FLASH_GOLDEN_N)
I2C1_SCL: U27.E14(MSIO18PB1) ; also on sheet 12 24 31 32 33 50 51 53
I2C1_SDA: U27.E15(MSIO18NB1) ; also on sheet 12 24 31 32 33 50 51 53
IFC_AD0: U27.L4(MSIO87NB4) ; also on sheet 34 35
IFC_AD1: U27.R4(MSIO88PB4) ; also on sheet 34 35
IFC_AD2: U27.R5(MSIO88NB4) ; also on sheet 34 35
IFC_AD3: U27.P6(MSIO89PB4) ; also on sheet 34 35
IFC_AD4: U27.P7(MSIO89NB4) ; also on sheet 34 35
IFC_AD5: U27.P2(MSIO90PB4) ; also on sheet 34 35
IFC_AD6: U27.R2(MSIO90NB4) ; also on sheet 34 35
IFC_AD7: U27.P1(MSIO91PB4) ; also on sheet 34 35
IFC_AD8: U27.R1(MSIO91NB4) ; also on sheet 34 35
IFC_AD9: U27.R6(MSIO92PB4) ; also on sheet 34 35
IFC_AD10: U27.R7(MSIO92NB4) ; also on sheet 34 35
IFC_AD11: U27.M7(MSIO93PB4) ; also on sheet 34 35
IFC_AD12: U27.M6(MSIO93NB4) ; also on sheet 34 35
IFC_AD13: U27.M8(MSIO94PB4) ; also on sheet 34 35
IFC_AD14: U27.N8(MSIO94NB4) ; also on sheet 34 35
IFC_AD15: U27.N6(MSIO95PB4) ; also on sheet 34 35
IFC_AD16: U27.N5(MSIO95NB4) ; also on sheet 34
IFC_AD17: R5904.2 U27.T5(MSIO96PB4) ; also on sheet 34
IFC_AD18: R5903.2 ; also on sheet 34
IFC_AD19: R5902.2 ; also on sheet 34
IFC_AD20: R5898.2 ; also on sheet 34
IFC_AD21: R796.1 R5771.2 U27.T4(MSIO96NB4) ; also on sheet 34
IFC_AVD: U27.R10(MSIO100NB4) ; also on sheet 34 35
IFC_BCTL: U27.P9(MSIO99NB4) ; also on sheet 34
IFC_CLE: U27.K4(MSIO87PB4) ; also on sheet 34 35
IFC_CLK: U27.L5(MSIO84PB4/CCC_NE0_CLKI0) ; also on sheet 34
IFC_CS0_B: U27.T10(MSIO102NB4) ; also on sheet 34
IFC_CS1_B: U27.N9(MSIO103PB4) ; also on sheet 34
IFC_CS2_B: U27.N10(MSIO103NB4) ; also on sheet 34
IFC_CS3_B: U27.P11(MSIO104PB4) ; also on sheet 34
IFC_NAND_CS_B: U27.R12(MSIO106NB4) ; also on sheet 35
IFC_NAND_RB_B: U27.T13(MSIO107NB4) ; also on sheet 35
IFC_NAND_WE_B: U27.T12(MSIO107PB4) ; also on sheet 35
IFC_NOR_CS_B: U27.P12(MSIO108PB4) ; also on sheet 35
IFC_NOR_RB_B: U27.M11(MSIO109PB4) ; also on sheet 35
IFC_NOR_WE_B: U27.P13(MSIO108NB4) ; also on sheet 35
IFC_OE_B: U27.R9(MSIO100PB4) ; also on sheet 34 35
IFC_RB0_B: U27.M10(MSIO105NB4) ; also on sheet 34
IFC_RB1_B: U27.R11(MSIO106PB4) ; also on sheet 34
IFC_TE: U27.T9(MSIO102PB4) ; also on sheet 34
IFC_WE0_B: U27.N11(MSIO104NB4) ; also on sheet 34
IFC_WE2_B: U27.M9(MSIO105PB4) ; also on sheet 34
IFC_WP_B: U27.P8(MSIO99PB4) ; also on sheet 34 35
INT_PHY0_B: U27.A13(DDRIO30PB0) ; also on sheet 42
INT_PHY1_B: U27.A14(DDRIO30NB0) ; also on sheet 43
INT_RETIMER_B: U27.J12(MSIO3PB2) ; also on sheet 38
IRQ0_B: U27.D9(DDRIO35PB0) ; also on sheet 27
IRQ1_B: U27.E9(DDRIO35NB0) ; also on sheet 27
IRQ2_B: U27.B10(DDRIO37PB0) ; also on sheet 27
IRQ3_B: U27.C10(DDRIO37NB0) ; also on sheet 27
IRQ4_B: U27.D8(DDRIO38PB0) ; also on sheet 27
IRQ5_B: U27.E8(DDRIO38NB0) ; also on sheet 27
IRQ6_B: U27.C8(DDRIO40PB0) ; also on sheet 27
IRQ7_B: U27.C9(DDRIO40NB0) ; also on sheet 27
IRQ8_B: U27.A8(DDRIO42PB0) ; also on sheet 27
IRQ9_B: U27.B8(DDRIO42NB0) ; also on sheet 27
IRQ10_B: U27.D6(DDRIO43PB0) ; also on sheet 27
IRQ11_B: U27.D7(DDRIO43NB0) ; also on sheet 27
IRQ_CLOCK_B: U27.K12(MSIO3NB2) ; also on sheet 24
IRQ_FAN_B: U27.K16(MSIO4PB2) ; also on sheet 53
IRQ_RTC_B: U27.C4(MSIO54NB6) ; also on sheet 51
LED0: U27.G13(MSIO8NB2) ; also on sheet 54
LED1: U27.G12(MSIO8PB2) ; also on sheet 54
LED2: U27.H14(MSIO7NB2) ; also on sheet 54
LED3: U27.H13(MSIO7PB2) ; also on sheet 54
LED4: U27.J14(MSIO6NB2) ; also on sheet 54
LED5: U27.J13(MSIO6PB2) ; also on sheet 54
LED6: U27.K15(MSIO5NB2) ; also on sheet 54
LED7: U27.K14(MSIO5PB2) ; also on sheet 54
LRST_BUTTON_B: C522.1 R669.1 R671.2 SW6.1
MON_DDRCLK: U27.A15(DDRIO27PB0) ; also on sheet 25
MON_SYSCLK: U27.C13(DDRIO25NB0) ; also on sheet 25
ORIENT_ERR_B: U27.L13(MSIO2NB2) ; also on sheet 23
OVDD: R5771.1 R5898.1 R5902.1 R5903.1 R5904.1 ; also on sheet 11 18 20 21 24 25 27 34 35 36
PCBVER0: R5770.1 U27.R14(MSIO110NB4)
PCBVER1: R5769.1 U27.T14(MSIO110PB4)
PCBVER2: R5897.1 U27.M12(MSIO109NB4)
PLED_P0WER_ON_GRE: Q12.3(DRAIN) R665.2 SW5.5(L1)
PLED_POWER_ON: Q12.1(GATE) U27.A5(MSIO53NB6)
PLED_STANDBY: Q11.1(GATE) U27.B5(MSIO53PB6)
PLED_STANDBY_YEL: Q11.3(DRAIN) R666.2 SW5.6(L2)
PS_1V0_EN: U27.D13(MSIO17PB1) ; also on sheet 14
PS_1V0_PG: U27.D14(MSIO17NB1) ; also on sheet 14
PS_2V5_EN: U27.C1(MSIO61PB6) ; also on sheet 15
PS_2V5_PG: U27.B1(MSIO61NB6) ; also on sheet 15
PS_GVDD_EN: U27.A2(MSIO57NB6) ; also on sheet 11
PS_GVDD_PG: U27.D1(MSIO58PB6) ; also on sheet 11
PS_ON: Q13.1(GATE) R748.1 U27.L14(MSIO0PB2)
PS_ON_B: J9.16(PS_ON) Q13.3(DRAIN) R394.1
PS_OVDD_EN: U27.D2(MSIO58NB6) ; also on sheet 11
PS_OVDD_PG: U27.E2(MSIO59PB6) ; also on sheet 11
PS_PHY_1V8_EN: U27.D4(MSIO62PB6) ; also on sheet 15
PS_PHY_1V8_PG: U27.D3(MSIO62NB6) ; also on sheet 15
PS_POVDD_EN: U27.M5(MSIO84NB4) ; also on sheet 16
PS_POVDD_PG: U27.N3(MSIO85PB4) ; also on sheet 16
PS_VDD_EN: U27.B3(MSIO56NB6) ; also on sheet 12
PS_VDD_PG: U27.B2(MSIO57PB6) ; also on sheet 12
PS_VTT_EN: U27.E1(MSIO59NB6) ; also on sheet 13
PS_XVDD_EN: U27.G5(MSIO60PB6) ; also on sheet 14
PS_XVDD_PG: U27.F5(MSIO60NB6) ; also on sheet 14
QSC_CLK: TP193.1(TP) U27.G16(SC_SPI_CLK)
QSC_SDI: TP194.1(TP) U27.G15(SC_SPI_SDI)
QSC_SDO: TP195.1(TP) U27.H16(SC_SPI_SDO)
QSC_SS: TP192.1(TP) U27.H15(SC_SPI_SS)
QT2: TP290.1(TP) U27.B16(MSIO14PB1/GB5)
QT3: TP259.1(TP) U27.T3(MSIO97PB4)
RST_CLKGEN_B: U27.A3(MSIO55PB6) ; also on sheet 24
RST_I2CMUX_B: U27.A4(MSIO55NB6) ; also on sheet 39 50
RST_IFC_B: U27.J1(MSIOD75PB5) ; also on sheet 35
RST_MEM_B: U27.C5(MSIO54PB6) ; also on sheet 31 32 33
RST_PCIE_X4_B: U27.E5(MSIO52PB6) ; also on sheet 47
RST_PCIE_X8_B: U27.E6(MSIO52NB6) ; also on sheet 48
RST_PHY_1G_B: U27.C3(MSIO56PB6) ; also on sheet 42 43
RST_SPI_B: U27.J2(MSIOD75NB5) ; also on sheet 36
SW1_1: R5772.2 SW1.8(B1) U610.4(IN0)
SW1_2: R5773.2 SW1.7(B2) U610.5(IN1)
SW1_3: R5774.2 SW1.6(B3) U610.6(IN2)
SW1_4: R5775.2 SW1.5(B4) U610.7(IN3)
SW1_5: R5776.2 SW2.8(B1) U610.8(IN4)
SW1_6: R5777.2 SW2.7(B2) U610.9(IN5)
SW1_7: R5778.2 SW2.6(B3) U610.10(IN6)
SW1_8: R5779.2 SW2.5(B4) U610.11(IN7)
SW2_1: R5780.2 SW3.8(B1) U610.13(IN8)
SW2_2: R5781.2 SW3.7(B2) U610.14(IN9)
SW2_3: R5782.2 SW3.6(B3) U610.15(IN10)
SW2_4: R5783.2 SW3.5(B4) U610.16(IN11)
SW2_5: R5784.2 SW4.8(B1) U610.17(IN12)
SW2_6: R5785.2 SW4.7(B2) U610.18(IN13)
SW2_7: R5786.2 SW4.6(B3) U610.19(IN14)
SW2_8: R5787.2 SW4.5(B4) U610.20(IN15)
SW_PWR_B: C520.1 R670.1 U27.F3(MSIO65NB6)
SW_PWR_OUT: C523.1 R670.2 R672.2 SW5.4
SW_RST_B: R669.2 U27.L3(MSIO81PB4)
SWS_CLK: U27.G3(MSIO64PB6/GB1) U610.22(SCLK)
SWS_CS_B: U27.E4(MSIO63NB6) U610.21(~{CS})
SWS_IRQ_B: TP249.1(TP) U610.2(~{INT})
SWS_MISO: U27.G2(MSIO64NB6) U610.1(SDOUT)
THERM_FAULT_B: U27.M13(MSIO2PB2) ; also on sheet 51
THERM_WARN_B: U27.M16(MSIO1NB2) ; also on sheet 51
N30740588: TP196.1(TP) U27.E7(VREF0)
N30741197: C3697.2 C3698.2 U27.F11(CCC_NE0_NE1_HPMS_MDDR_PLL_VSSA)
N30744842: R5588.2 U250.7(HOLD#)
N30744844: R5589.2 U250.3(WPE#)
N32124491: JP8.1 U27.N4(MSIO82PB4/PROBE_A)
N32124494: JP8.2 U27.P4(MSIO82NB4/PROBE_B)
N34046443: JP8.3 U27.L2(MSIO83PB4/GB3)

Not connected (* = marked no-connect by the designer): J9 14(-12V_P14)* 20(-5V_P20)*; J105 4*; SW5 2* 3* MH1* MH2*; U27 A7(DDRIO45PB0/CCC_NE0_CLKI3)* A9(DDRIO50NB0/CCC_NE1_CLKI3)* A10(DDRIO50PB0)* A12(DDRIO32PB0)* B6(DDRIO49PB0/GB0)* B7(DDRIO45NB0)* B11(DDRIO33PB0)* B12(DDRIO32NB0)* B15(DDRIO27NB0)* C6(DDRIO49NB0/GB4)* C11(DDRIO33NB0)* C15(MSIO15PB1/GB6)* C16(MSIO14NB1)* D11(DDRIO28PB0)* D12(MSI16NB1)* E11(DDRIO28NB0)* F2(MSIO65PB6) F4(MSIO63PB6/GB2)* F12(MSIO11PB2/CCC_NE0_CLKI1)* F13(MSIO11NB2/CCC_NE0_CLKI2)* J4(MSIOD74NB5)* J5(MSIOD74PB5)* J16(MSIO4NB2)* M2(MSIO83NB4/GB7)* M3(MSIO81NB4/CCC_NE1_CLKI0)* N1(MSIO86NB4)*; U605 5(NC1)* 6(NC2)*; U606 4(NC)*; U607 4(SNS/NC)*

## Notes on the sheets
sheet 1
- T4240RDB-B
- » T4240
  » T4160
sheet 2
- Table of Contents
- Revisions
- 1
- Title Page
- Rev
- Description
- Date
- Approved
- 2
- Revision Control
- INFO
- 3
- Block Diagram
- DX1
- Release A055
- 2023_0227
- G. Milliorn
- 4
- Stackup; Revision Notes
- DX2
- 1. CS4340 (obsolete/LL) changed to 2x TI DS100DF410
  2. Clock for CS4340 (MC100LVEP14DTG) deleted.
  3. U599/IDR 8L30205NLGI (52W) deleted.
  4. Updated U130 to prog. part (SI5341B-D15297-GM).
  5. Replaced T4240 assembly with T4240 alone.
  6. Replaced obs. SATA connector w/Molex 67800-5025
  7. Replaced obs. AT24C02 w/24AA025UID-I/SN (2x).
- 2023_0321
- G. Milliorn
- 5
- Info
- 6
- ATX Power Entry + Mechanical
- 7
- Power Supplies: Standby & Battery
- FPGA +
  CONFIG
- 8
- System FPGA: IO Ports
- 9
- System FPGA: Power
- 10
- Switches and Config
- 11
- Power Supplies: GVDD & OVDD
- DX3+
- 1. Replace SD translator.
  2. Remove NAND flash and change device.
  3. Add pullups to EVT* and pulldowns to SD*_RX if unused.
  4. Increase 10G SD caps to 0.22uF
  5. Replace SYS/DDR clock select mux.
  6. Replace obsolete enet jacks with BEL
- 2023_0421
- G. Milliorn
- 12
- Power Supplies: VDD
- 13
- Power Supplies: DDR MVREF + VTT
- POWER
  SUPPLY
- 14
- Power Supplies: SVDD & XVDD
- 15
- Power Supplies: 2V5 & PHY 1V8
- 16
- Power Supplies: Other
- 17
- -reserved-
- E
- Release A085
- 2023_1026
- G. Milliorn
- 18
- T4240: VDD Power
- T4240: SVDD & XVDD Power
- 19
- 20
- T4240: GVDD Power
- T4240
  POWER
- 21
- T4240: PLL Filters
- 22
- T4240: Grounds
- 23
- T4240: NC Pins
- 24
- Clock: System Clock Generator
- CLOCK
- 25
- Clock: PCIe Clocks & LS1088 Clocks
- 26
- -reserved-
- CONTROL
- 27
- T4240: System Block & COP
- 28
- T4240: DDR Controller #1
- 29
- T4240: DDR Controller #2
- 30
- T4240: DDR Controller #3
- DDR
- 31
- DIMM: DDR3 #1
- 32
- DIMM: DDR3 #2
- 33
- DIMM: DDR3 #3
- 34
- T4240: Local Bus Interface
- BOOT
  IO
- 35
- Flash: NOR and NAND
- 36
- T4240: SPI & SDHC Ports
- 37
- T4240: SerDes 1 & 2
- 38
- 10GE: DS100DF410 Retimers
- 10 G
  PHYS
- 39
- 10GE: SFP Monitor/Control
- 40
- SFP: Ports 1 & 2 & Cage
- 41
- SFP: Ports 3 & 4
- 42
- 1GE: 88E1143 PHY #1
- 1 G
  PHYS
- 43
- 1GE: 88E1143 PHY #2
- NOTES:
  1. All information is subject to change without notice.
     No warranty, expressed or applied, is made as to the
     accuracy of the information contained herein. This
     schematic is provided for reference purposes only.
     Contact your NXP representative to obtain the
     latest information on this product or related products.
  2. All resistors are 0402 1/10W 5% unless otherwise noted.
  3. All capacitors are 0402 X5R/X7R 10% unless otherwise noted.
  4. All components are 0C to 85C unless otherwise noted.
  5. PCB stackups are provided for reference only, and may
    be slightly modified by PCB vendor firms as needed.
  6. This design is not certified to industrial or automotive
     temperature ranges.  Components may be rated for
     AEC-Q200 but this is merely incidental.
  7. Errata corrections are noted with "E-nnnnn" in red boxes.
    For full details, consult the board errata: T4240RDB-ER
- 44
- 1GE: ENET Connectors 1:8
- T4240: EMI & RGMII Interfaces
- 45
- 46
- T4240: SerDes 3 & 4
- PCIe
- 47
- PCIe Slot #1: x4
- 48
- PCIe Slot #2: x8
- 49
- T4240: USB Interface
- 50
- I2C: Bus Translation
- 51
- I2C: Devices
- MISC
- 52
- Serial Ports
- 53
- Fan Controller & Headers
- 54
- Monitor LEDs
- 55
- Assembly Configuration
sheet 3
- BLOCK DIAGRAM
- x8 PCIe Slot
- x4 PCIe Slot
- P50
- P49
- PCIe X8
- PCIe X4
- 2.5 / 5 GT/s
- 2.5 / 5 GT/s
- SerDes3
  (ABCDEFGH)
- SerDes4
  (ABCD)
- SerDes4
  (G)
- 1.5 / 3 Gb/s
- 1866/2133MT/s
- CH A
- SATA Port
- DIMM 0
- DDR3 Bus
- SATA II
- P38
- P31
- 1866/2133MT/s
- DIMM 1
- DDR3 Bus
- CH B
- DDR3
- Freescale
  T4240 QorIQ
  Up to 1.8 GHz
- USB
  2.0
- 480Mbps
- USB x 2
- P32
- USB 2.0
- P51
- 1866/2133MT/s
- DIMM 2
- DDR3 Bus
- CH C
- P33
- UART
- Serial Port (RJ45) x 2
- RS232
- FPGA
  MICROSEMI
  M2GL005-VFG256
- P18-23/27-30/34/36/37/47/48/51
- P54
- Local Bus
- IFC
- P8-9
- SerDes1
  (ABCD)
- SerDes1
  (EFGH)
- SerDes2
  (ABCD)
- SerDes2
  (EFGH)
- I2C
- EEPROM
  MICROCHIP
  2Kb 24AA025UID x2
- SDHC
- I2C Bus
- NAND Flash 2GB
  Micron
  MT29F16G08ABABA
- P53
- P35
- RTC
  Maxim
  DS1374
- SGMII Bus
- SGMII Bus
- NOR Flash 128MB
  CYPRESS
  S29GL01GT11TFIV10
- 1.25Gbps
- 1.25 Gbps
- P53
- P35
- THERM
  ONSEMI
  ADT7481ARMZ
- SD interface
- XFI bus
- P53
- SD Card
- P36
- 10.3125 Gbps
- 4 Port 1G BaseT
  Marvell 88E1543
- 4 Port 1G BaseT
  Marvell 88E1543
- 2 Port 10G
  TI DS100DF410
- 2 Port 10G
  TI DS100DF410
- P44
- P45
- P38
- P38
- RJ45
- RJ45
- RJ45
- RJ45
- RJ45
- RJ45
- RJ45
- RJ45
- SFP+
- SFP+
- SFP+
- SFP+
- PORT 1
- PORT 2
- PORT 3
- PORT 4
- PORT 5
- PORT 6
- PORT 7
- PORT 8
- PORT 1
- PORT 2
- PORT 3
- PORT 4
- 0
- 2
- 4
- 6
- 8
- 9
- 10
- 11
- 1
- 3
- 5
- 7
- ON main board SFP+
- ON main board RJ45
sheet 4
- STACKUP
sheet 5
- POWER TREE
- I2C DEVICE TREE
- I2C1
  +-- n/a        Header
  +-- 0x4C       ADT7481 Thermal Monitor
  +-- 0x4D       EMC2305 Fan Controller
  +-- 0x50       I2C Boot Rom, 2Kb
  +-- 0x51       PCF2131 Real-Time Clock
  +-- 0x52       DDR3 #1 SPD EEPROM
  +-- 0x54       DDR3 #2 SPD EEPROM
  +-- 0x56       DDR3 #3 SPD EEPROM
  +-- 0x57       System ID EEPROM, 256B
  +-- 0x63       LTC3882 (VDD)
  +-- 0x66/67    System Control FPGA BCSRs
  +-- 0x74       Si5341B Clock Synthesizer
  +-- 0x75       PCA9547 (I2C mux, level 2)
  +-- I2C1_CH0
      +-- 0x18   DS100DF410 Retimer #1
      +-- 0x19   DS100DF410 Retimer #2
  +-- I2C1_CH1
      +-- 0x50   SFP+ Cage #1 (10GE Retimer #1)
  +-- I2C1_CH2
      +-- 0x50   SFP+ Cage #1 (10GE Retimer #1)
  +-- I2C1_CH3
      +-- 0x50   SFP+ Cage #1 (10GE Retimer #2)
  +-- I2C1_CH4
      +-- 0x50   SFP+ Cage #1 (10GE Retimer #2)
  +-- I2C1_CH5
  +-- I2C1_CH6
      +-- ????   PCIe Slot #1
  +-- 0x50       SFP+ Cage #2 (25G PHY #2)
  +-- I2C1_CH7
      +-- 0x20   SFP Monitor/Control GPIO
      +-- 0x7C   SFP Monitor/Control Reset
  I2C2 - n/a
      +-- ????   PCIe Slot #2
  NOTE: All I2C addresses are 7-bit (no RW bit),
        as are used with uboot
sheet 6
- ATX POWER + MECH
- VCC_12_8P
  - Used only by VDD supply
sheet 7
- STANDBY POWER
- 3V3_SB
    3.3V @ 0.5A
- 1V8_SB
    1.8V @ 0.5A
- 1V2_SB
    1.2V @ 0.3A
sheet 8
- FPGA: IO PORTS
- cfg_xvdd_sel
- 3V3
- 1V8
- 3V3 I/PU
- 3V3
- 3V3 I/PU
- 1V8
- 1.8V
- CLE= cfg_rcwsrc8
- 0:7= cfg_gpin
- 3V3
- 8:15= cfg_rcwsrc0:7
- 16= cfg_svr1
- 17= cfg_svr0
- 21= cfg_dramtype
- 1V8
- TE= cfg_ifc_te
- PCB_VER[2:0]
  ============
  000= Rev "E"
sheet 9
- FPGA: POWER & PROGRAM
- Note: This is correct, the
         GND path is internal.
- IN-SYSTEM UPDATE OPTION
- FPGA IN-SYSTEM UPDATE OPTION
  ======================
  Route through header with no stubs.
  Header connects to FTDI CM232H as follows:
  J67p1 (CS)   FTDI pin  5 (brown)
  J67p2 (SCK)  FTDI pin  2 (orange)
  J67p3 (SDI)  FTDI pin  3 (yellow)
  J67p4 (SCK)  FTDI pin  2 (green)
  J67p5 (GND)  FTDI pin 10 (black)
- Or Winbond W25Q64JVSSIQ
sheet 10
- SWITCHES & CONFIG
- SW1[1]:   SYSCLK
  -------------------------------
  >0=  66 MHz
   1= 100 MHz
  SW1[2]:   DDRCLK
  -------------------------------
   0= 100 MHz
  >1= 133 MHz
- SW1[3]:   RST_MODE
  -------------------------------
   0= Ignore RESET_REQ_B
  >1= Restart on RESET_REQ_B
- SW1[4]:   -
  -------------------------------
  >1= default
- SW2[1:3]:  RCW_SRC
  --------------------------------
   000= NAND flash
  >001= NOR flash
   010= SPI flash
   011= HCD #10
   10X= reserved
   110= SD Card
   111= I2C
  SW2[4]:    GPIN[0]
  -------------------------------
  > 1 = software-defined
- SW3[1:3]: VBANK
  -------------------------------
  >000= NOR bank 0
    ...
   111= NOR bank 7
  SW3[4]:  rsvd
  -------------------------------
  >1= default
- SW4[1]:  AUTO_ON
  -------------------------------
   0 = always power up
  >1 = manual power up
  SW4[2]:  BYPASS_B
  -------------------------------
   0= ignore faults
  >1= default
  SW4[3]:  TESTSEL
  -------------------------------
   0= T4160 CPU
  >1= T4240 CPU
  SW4[4]:  SVR
  -------------------------------
   0= cfg_svr=00
  >1= cfg_svr=11
- 1.8V
- cfg_dram_type - IFC_AD21
  -------------------------
  >0= DDR3 (1.5V)
   1= DDR3L (1.35V)
  NOTE: Multiple other
  changes required.
  cfg_reserved = IFC_AD[20:17]
  >1= reserved
- RESET Button
- POWER Button
